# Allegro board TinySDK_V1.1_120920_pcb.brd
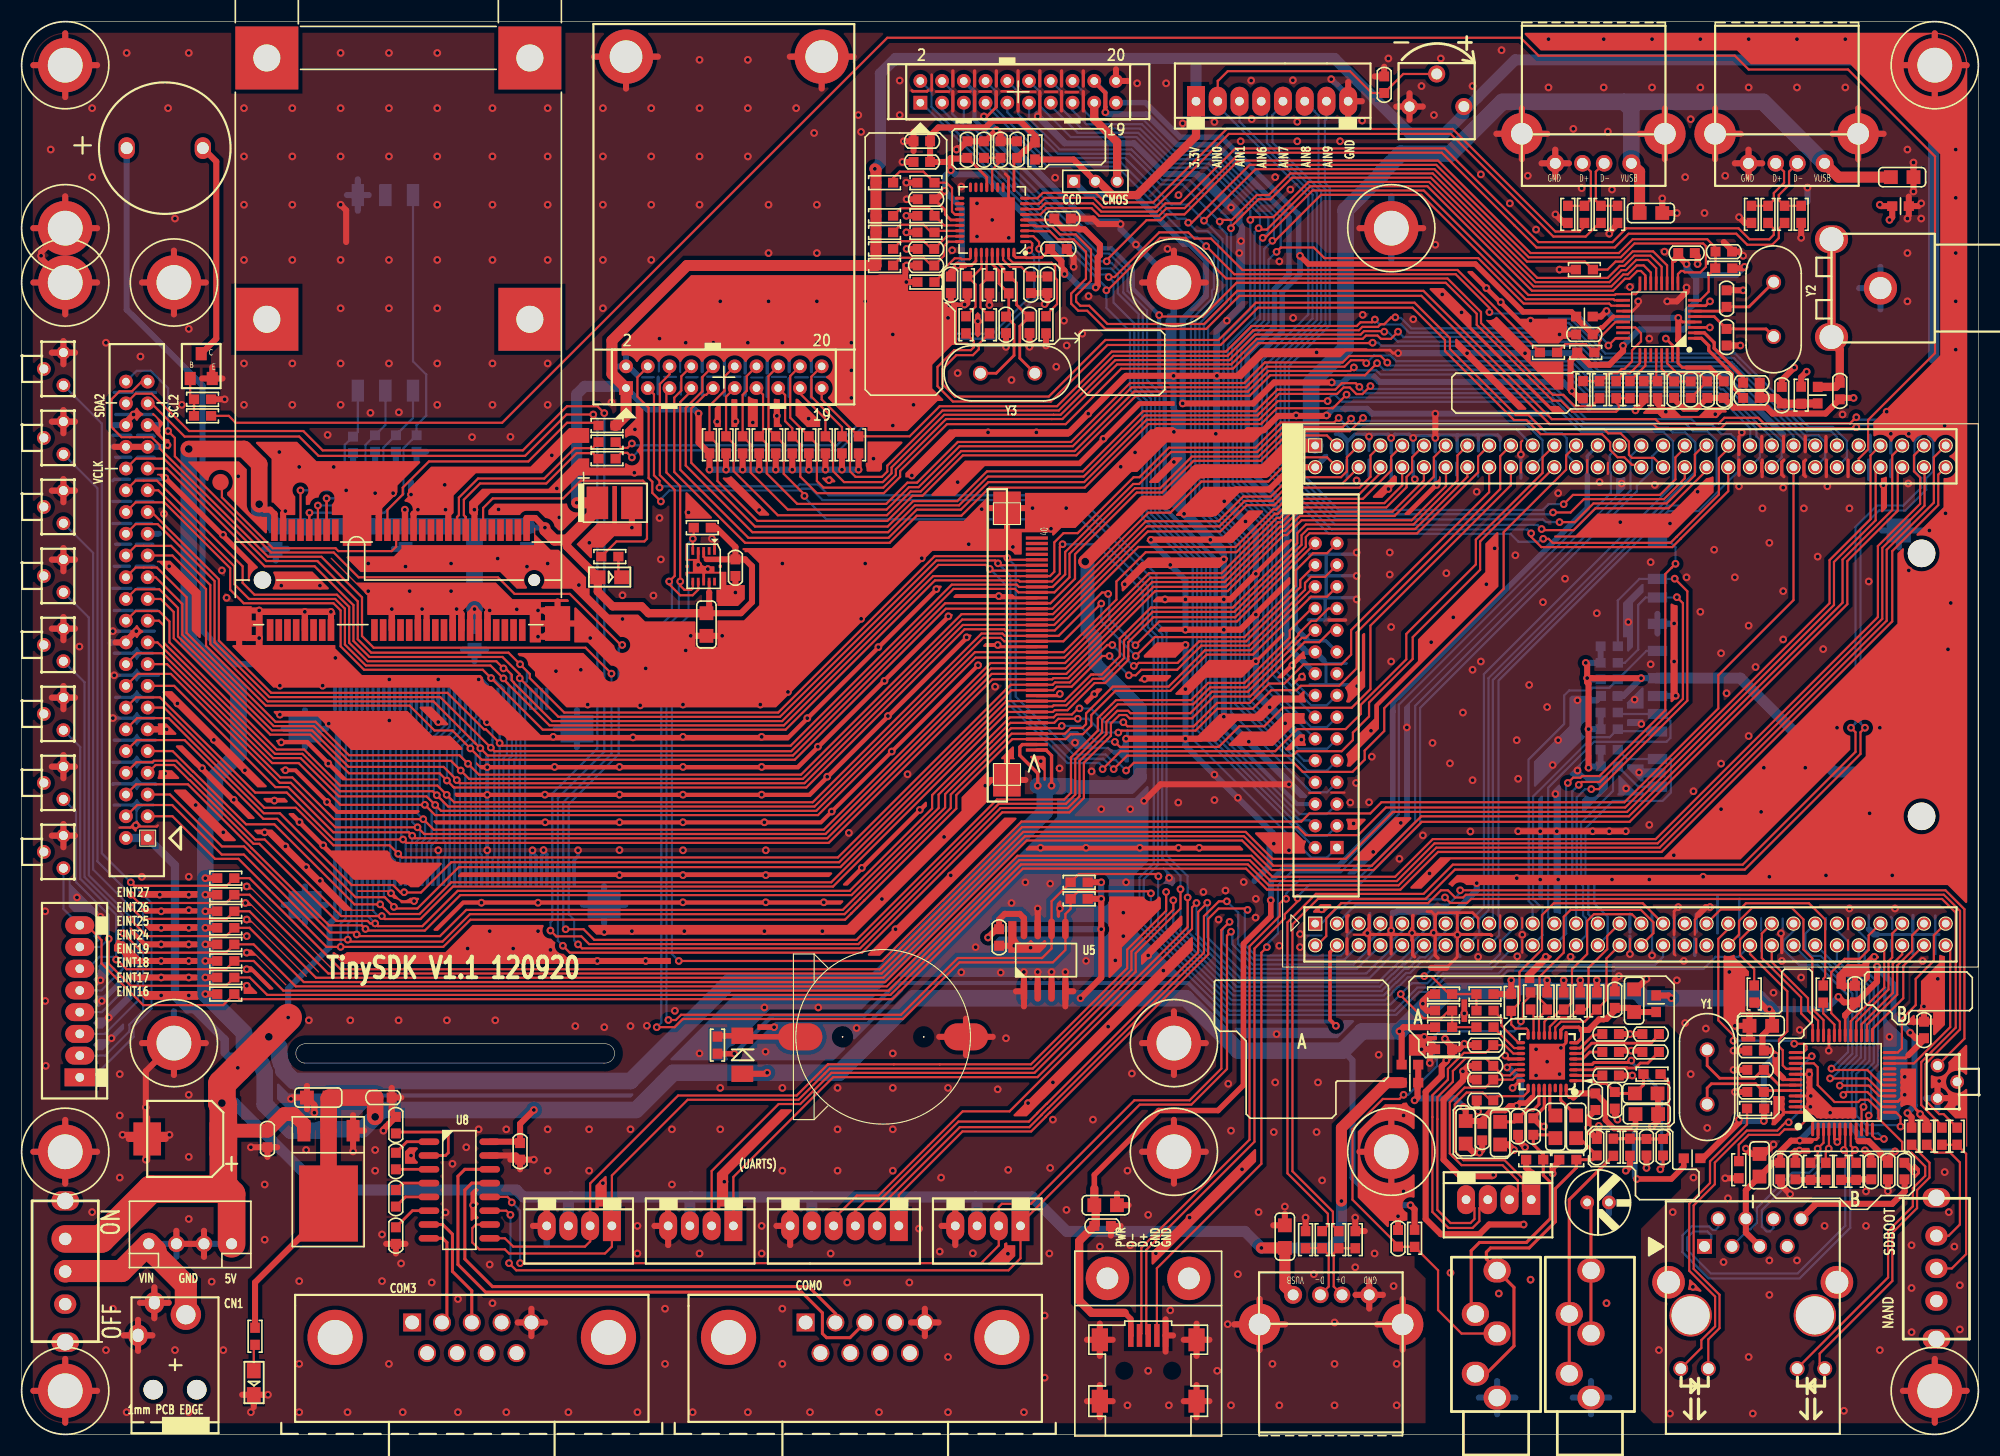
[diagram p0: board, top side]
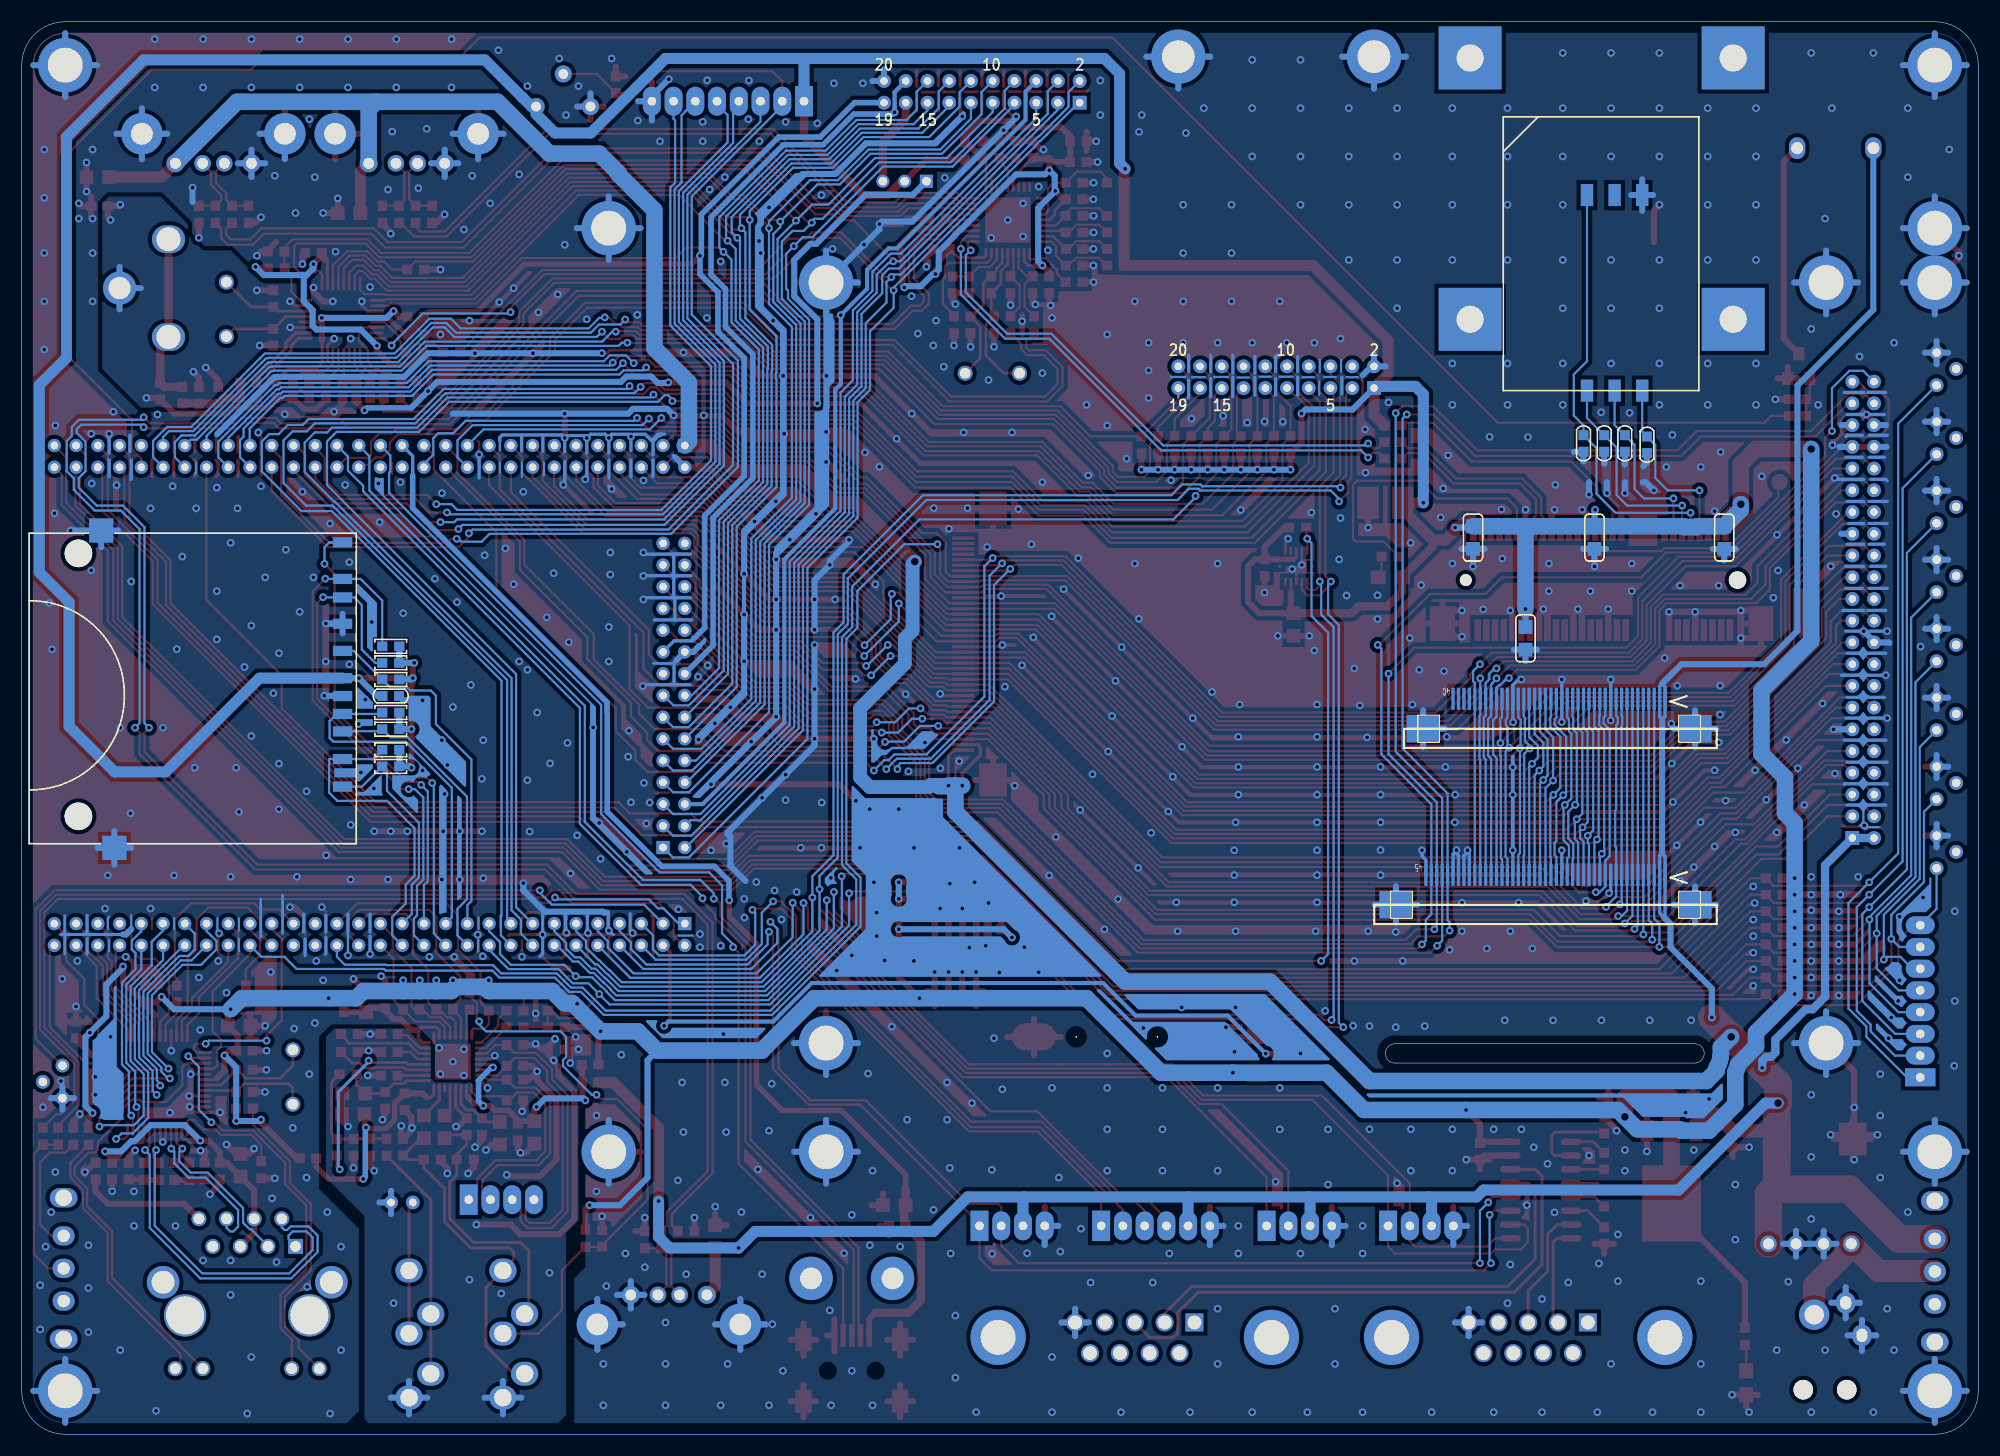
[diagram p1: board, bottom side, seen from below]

Outline 180 x 130 mm; copper layers: TOP, BOTTOM. Coordinates in mm from the lower left corner of the outline.
Outline path: 0,126 0,4 arc(1.17,1.17) 4,0 176,0 arc(178.83,1.17) 180,4 180,126 arc(178.83,128.83) 176,130 4,130 arc(1.17,128.83) 0,126 ; 26.01,35.94 53.57,35.94 arc(54.54,35.05) 53.57,34.16 26.01,34.16 arc(25.21,35.05) 26.01,35.94

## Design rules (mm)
net group DIFFPAIR42: nets XUHDM XUHDP
net group DIFFPAIR45: nets XUODM XUODP
net group DIFFPAIR46: nets DM9000_RX+ DM9000_RX-
net group DIFFPAIR47: nets DM9000_TX+ DM9000_TX-
net group DIFFPAIR48: nets N9616349 N9616353
net group DIFFPAIR49: nets N9609084 N9609088
net group DIFFPAIR50: nets DM2- DP2+
net group DIFFPAIR51: nets SPK_OUT_RN SPK_OUT_RP
net group DIFFPAIR52: nets SPK_OUT_LN SPK_OUT_LP
net group DIFFPAIR53: nets N9608868 N9608880
net group DIFFPAIR54: nets N9608680 N9608700
net group DIFFPAIR55: nets DM4- DP4+
net group 90OHM: nets N9607388 N9607392 USB_D+ USB_D-
net group PWR: nets N9607572

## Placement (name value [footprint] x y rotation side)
AVIN  -  [TVOUT]  166.5 109.98 180 top
BAT1  BATTERY  [BAT600]  71.63 36.58 90 top
BUZZER1  -  [SPEAKER]  9.91 118.37 0 top
C8  100uF/35V  [CAPSOP]  18.54 27.18 180 top
C9  104  [C0603]  22.61 27.94 270 top
C10  10uF  [C0805]  28.32 30.99 180 top
C11  104  [C0603]  32.51 30.99 0 top
C15  10uF/16V  [C0805]  161.04 37.59 180 top
C16  104  [C0603]  175.01 36.45 90 top
C17  104  [C0603]  168.66 39.75 90 top
C18  104  [C0603]  160.27 35.31 180 top
C19  15pF  [C0603]  160.28 33.54 180 top
C20  15pF  [C0603]  160.28 31.51 180 top
C21  104  [C0603]  173.21 24.99 270 top
C22  10uF/16V  [C0805]  159.88 23.72 90 top
C23  104  [C0603]  171.69 24.99 270 top
C24  104  [C0603]  161.78 24.99 270 top
C25  104  [C0603]  170.16 23.46 90 top
C26  104  [C0603]  163.18 23.46 90 top
C27  104  [C0603]  146.81 67.94 180 bottom
C28  104  [C0603]  89.92 46.48 270 top
C29  104  [C0603]  134.37 28.57 270 top
C30  10uF  [C0805]  132.84 28.83 270 top
C31  104  [C0603]  144.78 31.37 270 top
C32  10uF  [C0805]  148.46 29.46 0 top
C33  100pF  [C0603]  139.06 27.56 90 top
C34  100pF  [C0603]  144.91 25.65 90 top
C35  104  [C0603]  126.62 17.27 90 top
C36  1uF  [C0603]  151 27.18 270 top
C37  100pF  [C0603]  135.38 30.73 180 top
C38  100pF  [C0603]  135.38 32.64 180 top
C39  104  [C0603]  34.42 24.38 90 top
C40  104  [C0603]  34.42 29.21 270 top
C41  220pF  [C0603]  149.48 27.18 270 top
C42  1uF  [C0603]  149.1 35.18 0 top
C43  1uF  [C0603]  145.41 35.18 0 top
C44  1uF  [C0603]  145.41 33.02 0 top
C45  1uF  [C0603]  145.41 36.83 0 top
C46  1uF  [C0603]  150.62 36.83 180 top
C47  100pF  [C0603]  135.38 33.91 180 top
C48  100pF  [C0603]  135.38 35.81 180 top
C49  104  [C0603]  34.42 17.53 90 top
C50  104  [C0603]  146.56 39.24 90 top
C51  10uF/16V  [C0805]  98.68 21.08 0 top
C52  104  [C0603]  98.68 19.18 0 top
C53  104/NC  [C0603]  159.89 95.38 180 top
C54  10uF  [C0805]  148.34 38.86 90 top
C55  10uF  [C0805]  143 29.34 270 top
C56  10uF  [C0805]  141.1 29.34 270 top
C57  10uF  [C0805]  136.02 26.67 90 top
C58  104  [C0603]  137.67 29.08 270 top
C59  10uF  [C0805]  150.5 31.37 180 top
C60  104  [C0603]  146.56 31.5 270 top
C61  104  [C0603]  34.42 22.48 270 top
C62  104  [C0603]  65.66 78.99 90 top
C63  104  [C0603]  159.89 96.77 180 top
C64  104  [C0603]  125.35 123.44 90 top
C65  330pF  [C0603]  161.93 94.87 90 top
C67  10uF/16V  [C0805]  62.99 75.56 270 top
C68  104  [C0603]  45.85 26.8 270 top
C73  10u  [C0805]  171.96 115.7 0 top
C75  33pF  [C0603]  30.48 91.82 270 bottom
C76  33pF  [C0603]  34.42 91.95 270 bottom
C77  33pF  [C0603]  36.32 91.95 270 bottom
C78  33pF  [C0603]  32.51 91.95 270 bottom
C79  100uF  [C3528]  52.96 85.72 0 top
C80  104  [C0603]  83.57 117.09 180 top
C81  33pF  [C0603]  90.55 102.87 270 top
C82  104  [C0603]  85.47 106.55 270 top
C83  104  [C0603]  83.95 109.09 180 top
C84  104  [C0603]  92.84 106.55 270 top
C85  104  [C0603]  83.95 107.57 180 top
C86  104  [C0603]  95 111.89 0 top
C87  104  [C0603]  87 117.47 90 top
C88  104  [C0603]  91.57 117.47 90 top
C89  104  [C0603]  83.57 119 180 top
C90  1uF  [C0603]  94.36 106.55 270 top
C91  104  [C0603]  88.52 117.47 90 top
C92  1uF  [C0603]  90.05 117.47 90 top
C93  1uF  [C0603]  83.95 113.66 180 top
C94  1uF  [C0603]  94.62 109.09 0 top
C95  33pF  [C0603]  92.71 102.87 270 top
C96  10u  [C0805]  148.84 112.39 0 top
C97  10u  [C0805]  116.21 17.15 90 top
C104  330pF  [C0603]  167.26 96.77 270 top
C105  104  [C0603]  153.92 108.71 180 top
C106  104  [C0603]  143 101.22 0 top
C107  104  [C0603]  156.59 95.38 90 top
C108  22pF  [C0603]  156.84 103.76 90 top
C109  22pF  [C0603]  156.84 101.73 270 top
C110  1uF  [C0603]  153.54 96.9 270 top
C111  1uF  [C0603]  152.02 95.38 90 top
C112  1uF  [C0603]  155.07 95.38 90 top
C113  104  [C0603]  157.35 108.84 180 top
C142  10uF  [C0805]  23.37 83.57 270 bottom
C144  10uF  [C0805]  35.31 83.57 270 bottom
C145  10uF  [C0805]  41.66 74.3 270 bottom
C148  10uF  [C0805]  46.48 83.57 270 bottom
CAMERA  CON20A  [SDWIFI-NH]  91.67 123.55 0 top
CN1  DC_JACK  [DC023B]  14.1 6.35 90 top
COM0  CONNECTOR DB9  [DB9RA_M]  77.6 10.29 90 top
COM3  CONNECTOR DB9  [DB9RA_M]  41.4 10.29 90 top
CON1  CON4  [SIP4-FA2]  92.97 19.18 180 top
CON2  CON6  [SIP6-FA2]  75.69 19.18 180 top
CON3  CON4  [SIP4-FA2]  66.55 19.18 180 top
CON4  CON4  [SIP4-FA2]  55.37 19.18 180 top
CON5  CON4  [CON4-B]  15.5 17.53 180 top
CON6  CON8  [SIP8-FA2]  113.03 122.68 0 top
CON7  CON8  [SIP8-FA2]  5.34 37.85 90 top
CON8  MF210_miniPCIe  [MINI_PCIEX1-52P-4H]  34.65 78.62 0 top
CON10  SD/MMC CARD  [SDCARD]  169.04 61.98 0 bottom
CON12  J1X4_2.0PH  [SIP4-FA]  139.96 21.59 180 top
D1  4148  [D1206]  66.29 33.17 90 top
D4  GREEN LED  [LED]  53 78.86 0 top
FB1  0R/NC  [L0603]  127.71 34.02 0 top
FB2  0R  [L0603]  153.67 25.4 180 top
FB3  0R  [L0603]  127.71 32.36 0 top
FB5  0R  [L0603]  150.37 39.62 270 top
H1  CON1  [H1]  4 4 0 top
H2  CON1  [H1]  4 126 0 top
H3  CON1  [H1]  176 126 0 top
H4  CON1  [H1]  176 4 0 top
H5  CON1  [H1]  4 26 0 top
H6  CON1  [H1]  106 26 0 top
H7  CON1  [H1]  4 106 0 top
H8  CON1  [H1]  4 111 0 top
H9  CON1  [H1]  14 36 0 top
H10  CON1  [H1]  14 106 0 top
H11  CON1  [H1]  106 36 0 top
H12  CON1  [H1]  126 26 0 top
H13  CON1  [H1]  106 106 0 top
H14  CON1  [H1]  126 111 0 top
J1  CON3  [SIP3S]  96.78 115.32 0 top
K1  SW PUSHBUTTON  [KEY-A06]  2.03 98.05 270 top
K2  SW PUSHBUTTON  [KEY-A06]  2.03 91.7 270 top
K3  SW PUSHBUTTON  [KEY-A06]  2.03 85.35 270 top
K4  SW PUSHBUTTON  [KEY-A06]  2.03 79 270 top
K5  SW PUSHBUTTON  [KEY-A06]  2.03 72.65 270 top
K6  SW PUSHBUTTON  [KEY-A06]  2.03 66.3 270 top
K7  SW PUSHBUTTON  [KEY-A06]  2.03 59.95 270 top
K8  SW PUSHBUTTON  [KEY-A06]  2.03 53.6 270 top
L6  3.3uH/0R  [L0603]  165.23 95.63 270 top
L8  0R  [L0603]  143.76 102.87 0 top
L9  0R  [L0603]  172.85 113.03 0 top
LAN1  -  [HR911105A]  159.26 21.44 180 top
LCD1  LCD-888  [CON-FPC-P05-45P]  25.65 52.45 0 bottom
LCD2  LCD-888  [CON-FPC-P05-40P]  94.36 59.82 90 top
LCD3  LCD-888  [CON-FPC-P05-40P]  25.65 68.66 0 bottom
LCD4  CON44A  [IDC44S2]  10.42 74.42 90 top
LED_3.3  RED  [LED]  21.34 5.84 270 top
MIC1  MIC  [MIC2]  144.02 21.34 0 top
MIC2  PHONEJACK STEREO SW  [EARJACK5]  144.27 16.24 270 top
MINIUSB1  USBOTG  [MINIUSB_ANT]  103.63 5.84 0 top
P1  SIMCARD  [SIM-0011]  36.2 114.05 180 bottom
PERST_N  TP  [PADC15]  18.29 87.63 0 top
Q2  3904  [SOT-23-Q]  16.51 98.31 0 top
R1  0R  [R0603]  176.66 27.43 90 top
R2  0R  [R0603]  178.05 27.43 270 top
R3  0R  [R0603]  175.26 27.43 270 top
R4  1K  [R0603]  21.46 9.02 270 top
R5  10K  [R0603]  159.38 40.51 270 top
R6  1K  [R0603]  16.64 93.73 0 top
R7  0R  [R0603]  165.74 40.51 90 top
R8  6.8K,1%  [R0603]  157.97 24.35 270 top
R9  10K  [R0603]  97.28 50.8 180 top
R10  10K  [R0603]  97.28 49.28 180 top
R11  100K  [R0603]  64.01 35.81 270 top
R12  10K  [R0603]  64.8 91.06 270 top
R13  10K  [R0603]  67.84 91.06 270 top
R14  10K  [R0603]  70.89 91.06 270 top
R16  10K  [R0603]  16.64 95.25 180 top
R18  10K  [R0603]  73.94 91.06 270 top
R19  10K  [R0603]  76.99 91.06 270 top
R20  1K  [R0603]  159.51 29.98 180 top
R21  1K  [R0603]  173.86 27.43 270 top
R23  10K  [R0603]  66.32 91.06 90 top
R24  51R  [R0603]  167.37 24.2 270 top
R25  51R  [R0603]  168.77 24.2 270 top
R26  51R  [R0603]  164.57 24.2 270 top
R27  10K  [R0603]  63.27 91.06 90 top
R28  10K  [R0603]  69.37 91.06 90 top
R29  51R  [R0603]  165.97 24.2 270 top
R30  4.7K  [R0603]  62.61 83.44 180 top
R31  4.7K  [R0603]  134.62 40.51 0 top
R32  4.7K  [R0603]  130.81 38.99 180 top
R34  10K  [R0603]  72.42 91.06 90 top
R35  10K  [R0603]  18.77 51.18 180 top
R37  10K  [R0603]  18.77 49.66 180 top
R38  10K  [R0603]  146.05 62.99 180 bottom
R39  10K  [R0603]  18.77 48.13 180 top
R40  10K  [R0603]  18.77 46.61 180 top
R41  10K  [R0603]  146.05 69.47 180 bottom
R42  10K  [R0603]  146.05 64.9 180 bottom
R43  10K  [R0603]  18.77 45.09 0 top
R46  10K  [R0603]  142.24 25.27 0 top
R47  10K  [R0603]  139.19 25.27 0 top
R49  100K  [R0603]  128.14 18.03 90 top
R51  75R  [R0603]  163.7 95.63 90 top
R57  0R  [R0603]  134.62 38.99 0 top
R58  0R  [R0603]  134.62 37.47 0 top
R59  2.2K  [R0603]  149.99 33.15 180 top
R60  10K  [R0603]  75.46 91.06 90 top
R62  47K/NC  [R0603]  147.96 26.42 90 top
R63  0R  [R0603]  130.81 35.43 0 top
R64  10K  [R0603]  18.77 43.56 0 top
R65  10K  [R0603]  18.77 42.04 0 top
R66  10K  [R0603]  18.77 40.51 0 top
R67  100R  [R0603]  146.43 26.42 90 top
R71  10K  [R0603]  146.05 66.42 180 bottom
R72  10K  [R0603]  146.05 72.52 180 bottom
R73  10K  [R0603]  146.05 70.99 180 bottom
R74  10K  [R0603]  146.05 61.47 180 bottom
R75  10K  [R0603]  53.85 92.84 0 top
R76  200R  [R0603]  54.1 80.77 0 top
R80  22R  [R0603]  53.85 89.79 0 top
R81  22R  [R0603]  53.85 91.31 0 top
R82  0R  [R0603]  89.03 102.11 270 top
R89  22R  [R0603]  162.18 112.27 90 top
R90  22R  [R0603]  160.66 112.27 90 top
R91  NC  [R0603]  163.71 112.27 270 top
R92  0R  [R0603]  138.81 39.88 270 top
R93  NC  [R0603]  159.13 112.27 270 top
R94  NC  [R0603]  146.81 112.27 270 top
R95  22R  [R0603]  145.29 112.27 90 top
R96  0R  [R0603]  86.87 102.11 270 top
R97  22R  [R0603]  143.77 112.27 90 top
R99  NC  [R0603]  142.24 112.27 270 top
R107  NC  [R0603]  79.38 112.14 180 top
R108  NC  [R0603]  79.38 115.19 180 top
R109  NC  [R0603]  118.11 17.91 90 top
R110  22R  [R0603]  119.64 17.91 270 top
R111  10K  [R0603]  83.19 106.04 0 top
R112  22R  [R0603]  121.16 17.91 270 top
R113  NC  [R0603]  122.68 17.91 90 top
R114  10K  [R0603]  79.38 109.09 180 top
R115  10K  [R0603]  83.19 110.61 0 top
R116  10K  [R0603]  83.19 112.14 0 top
R117  10K  [R0603]  83.19 115.19 0 top
R118  0R  [R0603]  93.22 118.11 270 top
R119  0R  [R0603]  79.38 107.57 180 top
R121  12K,1%  [R0603]  94.24 102.11 270 top
R126  NC  [R0603]  130.81 37.47 180 top
R127  NC  [R0603]  130.81 40.51 180 top
R128  10K  [R0603]  137.03 39.75 90 top
R129  10K  [R0603]  140.34 39.88 90 top
R130  1M  [R0603]  90.81 105.79 90 top
R131  10K  [R0603]  141.86 39.88 90 top
R132  10K  [R0603]  143.38 39.88 90 top
R133  10K  [R0603]  144.91 39.88 90 top
R134  NC  [R0603]  79.38 110.61 180 top
R135  NC  [R0603]  89.03 105.79 270 top
R136  NC  [R0603]  87 105.79 270 top
R137  0R  [R0603]  147.96 96.14 270 top
R138  NC  [R0603]  146.69 96.14 270 top
R139  10K  [R0603]  143.76 107.19 0 top
R140  0R  [R0603]  140.46 99.57 0 top
R141  0R  [R0603]  145.16 96.14 90 top
R142  10K  [R0603]  150.5 96.14 90 top
R143  1.2K/NC  [R0603]  143.89 99.57 0 top
R144  1.2K/NC  [R0603]  143.64 96.14 270 top
R145  0R  [R0603]  149.22 96.14 90 top
R146  10K  [R0603]  156.59 107.31 180 top
RST  SW PUSHBUTTON  [KEY-A06]  178.05 32.44 90 top
S1  SW-DIP4  [SW35]  4 15 270 top
S2  SW-DIP4  [SW35]  176.15 15.24 90 top
SDIO  CON20A  [SDWIFI-2H]  64.59 97.28 0 top
SPK1  PHONEJACK STEREO SW  [EARJACK5]  135.64 16.24 270 top
TINY210  TinyCore  [TINY6410_2]  116 43 0 top
U2  AMS1086CM-3.3  [TO-252]  30.48 27.94 180 top
U4  DM9000AEP  [LQFP48FA]  167.51 32.38 0 top
U5  AT24LC04  [SOP8]  92.2 40.77 90 top
U6  WM8960GEFL  [QFN32-19P7-TH]  140.34 34.29 180 top
U7  MMA7660FC  [DFN10-19P7X111-2TH]  62.74 79.88 180 top
U8  SP3232  [SOP16]  37.47 26.92 0 top
U9  TVP5150  [S-PQFP-G32]  150.62 102.62 180 top
U11  USB2514B_QFN36_MIN  [QFN36-19P7]  89.28 111.76 180 top
USBH1  USB  A  [USB-A2]  165.86 116.97 0 top
USBH2  USB  A  [USB-A2]  148.08 116.97 0 top
USBH3  USB  A  [USB-A2]  116.97 12.83 180 top
W1  10K  [VR3_7X7]  129.03 123.19 0 top
Y1  25MHz  [OSC2PR-1]  155.06 35.32 270 top
Y2  14.31818MHz  [OSC2PR-1]  161.18 101.09 90 top
Y3  24MHz  [OSC2PR-1]  88.27 97.65 0 top

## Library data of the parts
AVIN = TVOUT
BAT1 = BATTERY_3
BUZZER1 = SPEAKER
C8 C10 C15 C22 C51 C67 C79 = CAP
C9 C11 C16-C21 C23-C50 C52-C65 C68 C73 C75-C78 C80 C82-C89 C91 C96 C97 C104-C113 C142 C144 C145 C148 = CAP NP
C81 C94 C95 = C
C90 C92 = 1.0uF-6.3V-10%-X5R-0402
C93 = 1.0uF-16V-10%-X5R-0603
CAMERA = CON20A
CN1 = CON3_3
COM0 COM3 = CONNECTOR DB9_2
CON1 CON3-CON5 = CON4
CON2 = CON6
CON6 CON7 = CON8
CON8 = CON50A_5
CON10 = SD_0
CON12 = J1X4_1
D1 = DIODE
D4 LED_3.3 = LED
FB1-FB3 FB5 L6 L8 L9 = INDUCTOR
H1-H14 = CON1
J1 = CON3
K1-K8 RST = SW PUSHBUTTON_0
LAN1 = HR911105A
LCD1 = LCD-888_1
LCD2 LCD3 = LCD-888_2
LCD4 = CON40A_0
MIC1 = MIC
MIC2 SPK1 = PHONEJACK STEREO SW
MINIUSB1 = USB_A/B_2
P1 = SIMCARD_0
PERST_N = TP
Q2 = NPN-BEC
R1-R14 R16 R18-R21 R23-R32 R34 R35 R37-R43 R46 R47 R49 R57-R60 R62-R67 R71-R76 R80-R82 R89-R97 R99 R107-R119 R126-R136 = R
R51 R137-R146 = RESISTOR
R121 = 12.0K-1/16W-1%-0603
S1 S2 = CON5
SDIO = CON20A_4
TINY210 = TinyCore
U2 = AMS1117
U4 = DM9000AEP
U5 = AT24LC04
U6 = WM8960GEFL_0
U7 = MMA7660FC
U8 = SP3232
U9 = TVP5150
U11 = USB2514B_QFN36_MIN
USBH1-USBH3 = USBPORT_0
W1 = RESISTOR VAR_0
Y1-Y3 = CRYSTAL

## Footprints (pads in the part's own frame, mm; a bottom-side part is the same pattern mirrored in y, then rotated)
BAT600
  oval 2.489x4.064 smd: 1(0,0) 2(0,-15.24)
  round 0.127 hole 1.194: 3(0,-3.886) 4(0,-11.354)
C0603
  rect 0.914x0.914 smd: 1(0,0) 2(1.524,0)
C0805
  rect 1.27x1.27 smd: 1(0,0) 2(2.083,0)
C3528
  rect 1.981x2.997 smd: 1(0,0) 2(3.175,0)
CAPSOP
  rect 2.54x3.048 smd: 1(0,0) 2(7,0)
CON4-B
  round 1.524 hole 1.016: 1(-3.81,0) 2(-1.27,0) 3(1.27,0) 4(3.81,0)
CON-FPC-P05-40P
  rect 0.305x2.032 smd: 1(3.16,0.968) 2(3.66,0.968) 3(4.16,0.968) 4(4.66,0.968) 5(5.16,0.968) 6(5.66,0.968) 7(6.161,0.968) 8(6.661,0.968) 9(7.161,0.968) 10(7.661,0.968) 11(8.161,0.968) 12(8.661,0.968) 13(9.161,0.968) 14(9.661,0.968) 15(10.162,0.968) 16(10.662,0.968) 17(11.162,0.968) 18(11.662,0.968) 19(12.162,0.968) 20(12.662,0.968) 21(13.162,0.968) 22(13.662,0.968) 23(14.163,0.968) 24(14.663,0.968) 25(15.163,0.968) 26(15.663,0.968) 27(16.163,0.968) 28(16.663,0.968) 29(17.163,0.968) 30(17.663,0.968) 31(18.164,0.968) 32(18.664,0.968) 33(19.164,0.968) 34(19.664,0.968) 35(20.164,0.968) 36(20.664,0.968) 37(21.164,0.968) 38(21.664,0.968) 39(22.165,0.968) 40(22.665,0.968)
  rect 3.048x2.54 smd: A(0.399,3.726) B(25.42,3.713)
CON-FPC-P05-45P
  rect 0.305x2.032 smd: 1(3.16,0.968) 2(3.66,0.968) 3(4.16,0.968) 4(4.66,0.968) 5(5.16,0.968) 6(5.66,0.968) 7(6.16,0.968) 8(6.661,0.968) 9(7.161,0.968) 10(7.661,0.968) 11(8.161,0.968) 12(8.661,0.968) 13(9.161,0.968) 14(9.661,0.968) 15(10.161,0.968) 16(10.662,0.968) 17(11.162,0.968) 18(11.662,0.968) 19(12.162,0.968) 20(12.662,0.968) 21(13.162,0.968) 22(13.662,0.968) 23(14.163,0.968) 24(14.663,0.968) 25(15.163,0.968) 26(15.663,0.968) 27(16.163,0.968) 28(16.663,0.968) 29(17.163,0.968) 30(17.663,0.968) 31(18.163,0.968) 32(18.664,0.968) 33(19.164,0.968) 34(19.664,0.968) 35(20.164,0.968) 36(20.664,0.968) 37(21.164,0.968) 38(21.664,0.968) 39(22.164,0.968) 40(22.665,0.968) 41(23.165,0.968) 42(23.665,0.968) 43(24.165,0.968) 44(24.665,0.968) 45(25.165,0.968)
  rect 3.048x2.54 smd: A(0.399,3.726) B(27.92,3.714)
D1206
  rect 1.5x2 smd: 1(0.009,-0.006) 2(3.51,-0.006)
DB9RA_M
  rect 1.651x1.651 hole 1.27: 1(0,5.486)
  round 1.651 hole 1.27: 2(0,2.743) 3(0,0) 4(0,-2.743) 5(0,-5.486) 6(-2.819,4.115) 7(-2.819,1.372) 8(-2.819,-1.372) 9(-2.819,-4.115)
  round 5.08 hole 3.2: 10(-1.372,12.573) 11(-1.372,-12.573)
DC023B
  round 1.803 hole 1.803 unplated: (-2.25,2) (-2.25,-2)
  round 2.794 hole 1.778: 1(4.65,-1)
  oval 1.981x1.778 hole 1.219x1.016: 2(5.75,1.9) 3(2.75,3.4)
DFN10-19P7X111-2TH
  rect 0.254x0.711 smd: 1(-1,-1.412) 2(-0.5,-1.412) 3(0,-1.412) 4(0.5,-1.412) 5(1,-1.412) 6(1,1.412) 7(0.5,1.412) 8(0,1.412) 9(-0.5,1.412) 10(-1,1.412)
  rect 0.3x0.254 smd: M1(1.524,0) M2(-1.524,0)
EARJACK5
  oval 2.2x2.5 hole 1.6: 1(5.17,-1.903) 2(6.97,0.097) 3(1.17,0.097) 4(10.67,-1.903) 5(12.87,0.097)
H1
  round 5 hole 3.2: 1(0,0)
HR911105A
  round 3.9 hole 3.5 unplated: (-5.707,10.498) (5.723,10.498)
  rect 1.372x1.372 hole 0.991: 1(4.453,4.148)
  round 1.372 hole 0.991: 2(3.183,1.608) 3(1.913,4.148) 4(0.643,1.608) 5(-0.627,4.148) 6(-1.897,1.608) 7(-3.167,4.148) 8(-4.437,1.608) 9(6.633,15.398) 10(4.093,15.398) 11(-4.077,15.398) 12(-6.617,15.398)
  round 2.997 hole 2.1: M3(-7.737,7.448) M4(7.753,7.448)
IDC44S2
  rect 1.27x1.27 hole 0.7: 1(-19.547,-1.17)
  round 1.27 hole 0.7: 2(-19.547,0.83) 3(-17.547,-1.17) 4(-17.547,0.83) 5(-15.547,-1.17) 6(-15.547,0.83) 7(-13.547,-1.17) 8(-13.547,0.83) 9(-11.547,-1.17) 10(-11.547,0.83) 11(-9.547,-1.17) 12(-9.547,0.83) 13(-7.547,-1.17) 14(-7.547,0.83) 15(-5.547,-1.17) 16(-5.547,0.83) 17(-3.547,-1.17) 18(-3.547,0.83) 19(-1.547,-1.17) 20(-1.547,0.83) 21(0.453,-1.17) 22(0.453,0.83) 23(2.453,-1.17) 24(2.453,0.83) 25(4.453,-1.17) 26(4.453,0.83) 27(6.453,-1.17) 28(6.453,0.83) 29(8.453,-1.17) 30(8.453,0.83) 31(10.453,-1.17) 32(10.453,0.83) 33(12.453,-1.17) 34(12.453,0.83) 35(14.453,-1.17) 36(14.453,0.83) 37(16.453,-1.17) 38(16.453,0.83) 39(18.453,-1.17) 40(18.453,0.83) 41(20.453,-1.17) 42(20.453,0.83) 43(22.453,-1.17) 44(22.453,0.83)
KEY-A06
  round 1.27 hole 0.787: 1(1.5,1.8) 2(-1.5,1.8) 3(0,0)
L0603
  rect 0.94x0.889 smd: 1(-0.762,0) 2(0.762,0)
LED
  rect 1.4x1.27 smd: 1(-0.002,0.008) 2(2.207,0.008)
LQFP48FA
  oval 0.279x1.27 smd: 1(-2.75,-4.327) 2(-2.25,-4.327) 3(-1.75,-4.327) 4(-1.25,-4.327) 5(-0.75,-4.327) 6(-0.25,-4.327) 7(0.25,-4.327) 8(0.75,-4.327) 9(1.25,-4.327) 10(1.75,-4.327) 11(2.25,-4.327) 12(2.75,-4.327) 25(2.75,4.327) 26(2.25,4.327) 27(1.75,4.327) 28(1.25,4.327) 29(0.75,4.327) 30(0.25,4.327) 31(-0.25,4.327) 32(-0.75,4.327) 33(-1.25,4.327) 34(-1.75,4.327) 35(-2.25,4.327) 36(-2.75,4.327)
  oval 1.27x0.279 smd: 13(4.327,-2.75) 14(4.327,-2.25) 15(4.327,-1.75) 16(4.327,-1.25) 17(4.327,-0.75) 18(4.327,-0.25) 19(4.327,0.25) 20(4.327,0.75) 21(4.327,1.25) 22(4.327,1.75) 23(4.327,2.25) 24(4.327,2.75) 37(-4.327,2.75) 38(-4.327,2.25) 39(-4.327,1.75) 40(-4.327,1.25) 41(-4.327,0.75) 42(-4.327,0.25) 43(-4.327,-0.25) 44(-4.327,-0.75) 45(-4.327,-1.25) 46(-4.327,-1.75) 47(-4.327,-2.25) 48(-4.327,-2.75)
MIC2
  round 1.27 hole 0.711: 1(0,0) 2(2,0)
MINI_PCIEX1-52P-4H
  round 1.6 hole 1.6 unplated: (-12.5,0)
  rect 5.791x5.791 hole 2.489: (-12.1,48.05) (-12.1,24) (12.1,48.05) (12.1,24)
  round 1.092 hole 1.092 unplated: (12.5,0)
  rect 0.61x2.007 smd: 1(-11.8,-4.6) 2(-11.4,4.6) 3(-11,-4.6) 4(-10.6,4.6) 5(-10.2,-4.6) 6(-9.8,4.6) 7(-9.4,-4.6) 8(-9,4.6) 9(-8.6,-4.6) 10(-8.2,4.6) 11(-7.8,-4.6) 12(-7.4,4.6) 13(-7,-4.6) 14(-6.6,4.6) 15(-6.2,-4.6) 16(-5.8,4.6) 17(-2.2,-4.6) 18(-1.8,4.6) 19(-1.4,-4.6) 20(-1,4.6) 21(-0.6,-4.6) 22(-0.2,4.6) 23(0.2,-4.6) 24(0.6,4.6) 25(1,-4.6) 26(1.4,4.6) 27(1.8,-4.6) 28(2.2,4.6) 29(2.6,-4.6) 30(3,4.6) 31(3.4,-4.6) 32(3.8,4.6) 33(4.2,-4.6) 34(4.6,4.6) 35(5,-4.6) 36(5.4,4.6) 37(5.8,-4.6) 38(6.2,4.6) 39(6.6,-4.6) 40(7,4.6) 41(7.4,-4.6) 42(7.8,4.6) 43(8.2,-4.6) 44(8.6,4.6) 45(9,-4.6) 46(9.4,4.6) 47(9.8,-4.6) 48(10.2,4.6) 49(10.6,-4.6) 50(11,4.6) 51(11.4,-4.6) 52(11.8,4.6)
  rect 2.311x3.2 smd: M1(-14.65,-4) M2(14.65,-4)
MINIUSB_ANT
  round 4 hole 2 unplated: (-3.75,8.5) (3.75,8.5)
  round 0 hole 0.889 unplated: (-2.2,0) (2.2,0)
  rect 0.508x2.108 smd: 1(-1.6,3.25) 2(-0.8,3.25) 3(0,3.25) 4(0.8,3.25) 5(1.6,3.25)
  rect 1.499x2.108 smd: 6(4.45,2.85) 7(-4.45,2.85) 8(-4.45,-2.8) 9(4.45,-2.8)
OSC2PR-1
  round 1.372 hole 0.991: 1(-0.064,0) 2(4.94,0)
PADC15
  round 1.5 smd: 1(0,0)
QFN32-19P7-TH
  oval 0.813x0.305 smd: 1(-2.425,1.75) 2(-2.425,1.25) 3(-2.425,0.75) 4(-2.425,0.25) 5(-2.425,-0.25) 6(-2.425,-0.75) 7(-2.425,-1.25) 8(-2.425,-1.75) 17(2.425,-1.75) 18(2.425,-1.25) 19(2.425,-0.75) 20(2.425,-0.25) 21(2.425,0.25) 22(2.425,0.75) 23(2.425,1.25) 24(2.425,1.75)
  oval 0.305x0.813 smd: 9(-1.75,-2.425) 10(-1.25,-2.425) 11(-0.75,-2.425) 12(-0.25,-2.425) 13(0.25,-2.425) 14(0.75,-2.425) 15(1.25,-2.425) 16(1.75,-2.425) 25(1.75,2.425) 26(1.25,2.425) 27(0.75,2.425) 28(0.25,2.425) 29(-0.25,2.425) 30(-0.75,2.425) 31(-1.25,2.425) 32(-1.75,2.425)
  rect 3.302x3.302 smd: G1(0,0)
QFN36-19P7
  oval 0.889x0.279 smd: 1(-3,2) 2(-3,1.5) 3(-3,1) 4(-3,0.5) 5(-3,0) 6(-3,-0.5) 7(-3,-1) 8(-3,-1.5) 9(-3,-2) 19(3,-2) 20(3,-1.5) 21(3,-1) 22(3,-0.5) 23(3,0) 24(3,0.5) 25(3,1) 26(3,1.5) 27(3,2)
  oval 0.279x0.889 smd: 10(-2,-3) 11(-1.5,-3) 12(-1,-3) 13(-0.5,-3) 14(0,-3) 15(0.5,-3) 16(1,-3) 17(1.5,-3) 18(2,-3) 28(2,3) 29(1.5,3) 30(1,3) 31(0.5,3) 32(0,3) 33(-0.5,3) 34(-1,3) 35(-1.5,3) 36(-2,3)
  rect 4.166x4.166 smd: 37(0,0)
R0603
  rect 0.94x0.889 smd: 1(-0.787,0) 2(0.787,0)
S-PQFP-G32
  rect 1.27x0.254 smd: 1(-3.3,1.75) 2(-3.3,1.25) 3(-3.3,0.75) 4(-3.3,0.25) 5(-3.3,-0.25) 6(-3.3,-0.75) 7(-3.3,-1.25) 8(-3.3,-1.75) 17(3.3,-1.75) 18(3.3,-1.25) 19(3.3,-0.75) 20(3.3,-0.25) 21(3.3,0.25) 22(3.3,0.75) 23(3.3,1.25) 24(3.3,1.75)
  rect 0.254x1.27 smd: 9(-1.75,-3.3) 10(-1.25,-3.3) 11(-0.75,-3.3) 12(-0.25,-3.3) 13(0.25,-3.3) 14(0.75,-3.3) 15(1.25,-3.3) 16(1.75,-3.3) 25(1.75,3.3) 26(1.25,3.3) 27(0.75,3.3) 28(0.25,3.3) 29(-0.25,3.3) 30(-0.75,3.3) 31(-1.25,3.3) 32(-1.75,3.3)
SDCARD
  round 2.54 hole 2.54 unplated: (5.748,-19.095) (5.748,5.104)
  rect 1.778x0.94 smd: 1(-18.552,-0.168) 2(-18.552,-2.708) 3(-18.552,-5.967) 4(-18.552,-7.612) 5(-18.552,-10.119) 6(-18.552,-12.619) 7(-18.552,-15.039) 8(-18.552,-16.744) 9(-18.552,2.372) 10(-18.552,-20.104) 11(-18.552,-4.316)
  rect 2.235x2.235 smd: 12(2.438,8.009) 13(3.652,-21.199)
SDWIFI-2H
  rect 1.27x1.27 hole 0.7: 1(-9,-1)
  round 1.27 hole 0.7: 2(-9,1) 3(-7,-1) 4(-7,1) 5(-5,-1) 6(-5,1) 7(-3,-1) 8(-3,1) 9(-1,-1) 10(-1,1) 11(1,-1) 12(1,1) 13(3,-1) 14(3,1) 15(5,-1) 16(5,1) 17(7,-1) 18(7,1) 19(9,-1) 20(9,1)
  round 5 hole 3: A(9,29.5) B(-9,29.5)
SDWIFI-NH
  rect 1.27x1.27 hole 0.7: 1(-9,-1)
  round 1.27 hole 0.7: 2(-9,1) 3(-7,-1) 4(-7,1) 5(-5,-1) 6(-5,1) 7(-3,-1) 8(-3,1) 9(-1,-1) 10(-1,1) 11(1,-1) 12(1,1) 13(3,-1) 14(3,1) 15(5,-1) 16(5,1) 17(7,-1) 18(7,1) 19(9,-1) 20(9,1)
SIM-0011
  rect 1.143x2.032 smd: 1(5.28,-18) 2(2.74,-18) 3(0.2,-18) 4(5.28,0) 5(2.74,0) 6(0.2,0)
SIP3S
  rect 1.2x1.2 hole 0.8: 1(0,0)
  round 1.2 hole 0.8: 2(2,0) 3(4,0)
SIP4-FA
  rect 1.651x2.8 hole 0.8: 1(1.08,0)
  oval 1.651x2.667 hole 0.8: 2(3.08,0) 3(5.08,0) 4(7.08,0)
SIP4-FA2
  rect 1.651x2.8 hole 0.8: 1(1.08,0)
  oval 1.651x2.667 hole 0.8: 2(3.08,0) 3(5.08,0) 4(7.08,0)
SIP6-FA2
  rect 1.651x2.8 hole 0.8: 1(-5,0)
  oval 1.651x2.667 hole 0.8: 2(-3,0) 3(-1,0) 4(1,0) 5(3,0) 6(5,0)
SIP8-FA2
  rect 1.651x2.8 hole 0.8: 1(-5,0)
  oval 1.651x2.667 hole 0.8: 2(-3,0) 3(-1,0) 4(1,0) 5(3,0) 6(5,0) 7(7,0) 8(9,0)
SOP8
  oval 1.905x0.61 smd: 1(0,0) 2(0,-1.27) 3(0,-2.54) 4(0,-3.81) 5(5.74,-3.81) 6(5.74,-2.54) 7(5.74,-1.27) 8(5.74,0)
SOP16
  oval 1.905x0.61 smd: 1(0,0) 2(0,-1.27) 3(0,-2.54) 4(0,-3.81) 5(0,-5.08) 6(0,-6.35) 7(0,-7.62) 8(0,-8.89) 9(5.588,-8.89) 10(5.588,-7.62) 11(5.588,-6.35) 12(5.588,-5.08) 13(5.588,-3.81) 14(5.588,-2.54) 15(5.588,-1.27) 16(5.588,0)
SOT-23-Q
  rect 1.016x1.219 smd: B(-1.016,-1.143) C(0,1.143) E(1.016,-1.143)
SPEAKER
  oval 1.5x2 hole 1.1: 1(-0.254,0) 2(6.754,0)
SW35
  oval 1.778x2.54 hole 1.524: 1(-6.477,0) 5(6.523,0)
  oval 1.778x2.032 hole 1.143: 2(-2.977,0) 3(0.023,0) 4(3.023,0)
TINY6410_2
  rect 1.219x1.219 hole 0.711: A1(3,48) B1(3,4) C1(5,11)
  round 1.219 hole 0.711: A2(3,46) A3(5,48) A4(5,46) A5(7,48) A6(7,46) A7(9,48) A8(9,46) A9(11,48) A10(11,46) A11(13,48) A12(13,46) A13(15,48) A14(15,46) A15(17,48) A16(17,46) A17(19,48) A18(19,46) A19(21,48) A20(21,46) A21(23,48) A22(23,46) A23(25,48) A24(25,46) A25(27,48) A26(27,46) A27(29,48) A28(29,46) A29(31,48) A30(31,46) A31(33,48) A32(33,46) A33(35,48) A34(35,46) A35(37,48) A36(37,46) A37(39,48) A38(39,46) A39(41,48) A40(41,46) A41(43,48) A42(43,46) A43(45,48) A44(45,46) A45(47,48) A46(47,46) A47(49,48) A48(49,46) A49(51,48) A50(51,46) A51(53,48) A52(53,46) A53(55,48) A54(55,46) A55(57,48) A56(57,46) A57(59,48) A58(59,46) A59(61,48) A60(61,46) B2(3,2) B3(5,4) B4(5,2) B5(7,4) B6(7,2) B7(9,4) B8(9,2) B9(11,4) B10(11,2) B11(13,4) B12(13,2) B13(15,4) B14(15,2) B15(17,4) B16(17,2) B17(19,4) B18(19,2) B19(21,4) B20(21,2) B21(23,4) B22(23,2) B23(25,4) B24(25,2) B25(27,4) B26(27,2) B27(29,4) B28(29,2) B29(31,4) B30(31,2) B31(33,4) B32(33,2) B33(35,4) B34(35,2) B35(37,4) B36(37,2) B37(39,4) B38(39,2) B39(41,4) B40(41,2) B41(43,4) B42(43,2) B43(45,4) B44(45,2) B45(47,4) B46(47,2) B47(49,4) B48(49,2) B49(51,4) B50(51,2) B51(53,4) B52(53,2) B53(55,4) B54(55,2) B55(57,4) B56(57,2) B57(59,4) B58(59,2) B59(61,4) B60(61,2) C2(3,11) C3(5,13) C4(3,13) C5(5,15) C6(3,15) C7(5,17) C8(3,17) C9(5,19) C10(3,19) C11(5,21) C12(3,21) C13(5,23) C14(3,23) C15(5,25) C16(3,25) C17(5,27) C18(3,27) C19(5,29) C20(3,29) C21(5,31) C22(3,31) C23(5,33) C24(3,33) C25(5,35) C26(3,35) C27(5,37) C28(3,37) C29(5,39) C30(3,39)
TO-252
  rect 1.194x1.981 smd: 1(0,0) 2(2.261,0) 3(4.521,0)
  rect 5.41x7.01 smd: 4(2.261,6.706)
TVOUT
  oval 3.048x2.54 hole 2.21: 1(0,0) 2(0,9)
  round 3.048 hole 2.032: 3(-4.5,4.5)
USB-A2
  round 1.651 hole 1: 1(0,0) 4(-7,0)
  round 1.524 hole 1: 2(-2.504,0) 3(-4.498,0)
  round 3.81 hole 2: 5(3.084,2.718) 6(-10.074,2.718)
VR3_7X7
  round 1.575 hole 0.9: 1(-1.36,-1) 2(3.64,-1) 3(1.14,2)

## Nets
AGND: C29.2 C30.2 C31.2 C32.2 C33.2 C34.2 C37.2 C38.2 C41.2 C42.1 C43.2 C44.2 C45.2 C46.2 C47.2 C48.2 C57.1 C58.2 C59.1 C60.2 MIC1.2 MIC2.5(E) R46.1 R47.1 R62.1 R63.2 SPK1.5(E) U6.20(SPKGND2) U6.24(SPKGND1) U6.28(AGND)
AVDD_CCD_1.8V: C107.2 L8.2 U9.4(PLL_AVDD) U9.32(CH2_AVDD)
GND: BAT1.2(-) C8.2 C9.2 C10.2 C11.2 C15.2 C16.2 C17.2 C18.2 C19.2 C20.2 C21.1 C22.2 C23.2 C24.2 C25.2 C26.2 C27.2 C28.2 C35.2 C40.1 C49.1 C50.2 C51.2 C52.2 C54.2 C62.1 C64.2 C67.2 C68.2 C73.2 C75.2 C76.2 C77.2 C78.2 C79.2 C80.2 C81.2 C82.2 C83.2 C84.2 C85.2 C86.2 C87.2 C88.2 C89.2 C90.2 C91.2 C92.2 C93.2 C94.2 C95.2 C96.2 C97.2 C105.1 C106.1 C113.1 C142.2 C144.2 C145.2 C148.2 CAMERA.20 CN1.2 CN1.3 COM0.5 COM3.5 CON1.4 CON2.6 CON3.4 CON4.4 CON5.2 CON5.3 CON6.8 CON8.4(GND1) CON8.9(GND2) CON8.15(GND3) CON8.18(GND4) CON8.21(GND5) CON8.26(GND6) CON8.27(GND7) CON8.29(GND8) CON8.34(GND9) CON8.35(GND10) CON8.37(GND11) CON8.40(GND12) CON8.43(GND13) CON8.M1 CON8.M2 CON10.3(GND2) CON10.6(GND1) CON10.12(PAD1) CON10.13(PAD2) H1.1 H2.1 H3.1 H4.1 H5.1 H6.1 H7.1 H8.1 H9.1 H10.1 H11.1 H12.1 H13.1 H14.1 K1.2 K2.2 K3.2 K4.2 K5.2 K6.2 K7.2 K8.2 L9.2 LCD1.11(GND1) LCD1.20(GND2) LCD1.29(GND3) LCD1.37(GND4) LCD1.38(GND5) LCD1.39(GND6) LCD1.40(GND7) LCD1.45(GND8) LCD1.A LCD1.B LCD2.11(GND1) LCD2.20(GND2) LCD2.29(GND3) LCD2.A LCD2.B LCD3.11(GND1) LCD3.20(GND2) LCD3.29(GND3) LCD3.A LCD3.B LCD4.11 LCD4.20 LCD4.29 LCD4.37 LCD4.38 LCD4.39 LCD4.40 LED_3.3.2(CATHODE) MINIUSB1.5(GND) MINIUSB1.6(#6) MINIUSB1.7(#7) MINIUSB1.8(#8) MINIUSB1.9(#9) P1.4(GND) Q2.E(EMITTER) R3.1 R8.2 R16.1 R63.1 R91.2 R93.2 R94.2 R99.2 R109.2 R111.1 R113.2 R115.1 R116.1 R117.1 R121.2 R135.2 R136.2 R139.1 R142.1 RST.2 SDIO.2 SDIO.A SDIO.B TINY210.A2 TINY210.C20 U2.1(GND) U4.5(AGND2) U4.6(AGND3) U4.15(GND) U4.33(GND2) U4.41(TEST) U4.45(GND1) U4.47(AGND1) U4.48(BGGND) U5.1(A0) U5.2(A1) U5.3(A2) U5.4(GND) U5.7(WP) U6.9(DGND) U6.G1(GND_PADDLE) U7.1(RESERVED1) U7.4(AVSS) U7.8(DVSS) U8.15(VSS) U9.19(DGND) U11.11(TEST) U11.37(VSS(FLAG)) USBH1.4(GND1) USBH1.5(GND3) USBH1.6(GND2) USBH2.4(GND1) USBH2.5(GND3) USBH2.6(GND2) USBH3.4(GND1) USBH3.5(GND3) USBH3.6(GND2) W1.1(A)
GND_EARTH: C21.2 LAN1.8(CHS_GND)
VBAT: BAT1.1(+) D1.2(K) R11.1
VDD_3.3V: C10.1 C11.1 C15.1 C16.1 C17.1 C18.1 C27.1 C28.1 C62.2 C67.1 C68.1 C79.1 C142.1 C144.1 C145.1 C148.1 CON6.1 CON8.2(VDD_3V3A) CON8.24(VDD_3V3B) CON8.39(VDD_3V3C) CON8.41(VDD_3V3D) CON8.52(VDD_3V3E) CON10.4(VDD) D1.1(A) D4.1(ANODE) FB1.1 FB2.1 FB5.1 J1.2 R4.1 R5.2 R9.1 R10.1 R12.2 R13.2 R14.2 R18.2 R19.2 R20.1 R21.1 R23.1 R27.1 R28.1 R30.1 R31.2 R32.2 R34.1 R35.2 R37.2 R38.2 R39.2 R40.2 R41.2 R42.2 R43.1 R49.2 R60.1 R64.1 R65.1 R66.1 R71.2 R72.2 R73.2 R74.2 R75.2 R107.2 R108.2 R114.2 R118.2 R119.2 R126.2 R127.2 R128.2 R129.2 R131.2 R132.2 R133.2 R134.2 SDIO.1 U2.2(VOUT) U2.4(TAB) U4.23(VDD1) U4.30(VDD2) U4.42(VDD3) U5.8(VDD) U7.3(AVDD) U7.9(DVDD) U8.16(VDD) W1.2(B)
VDD_5V: BUZZER1.1 C8.1 C9.1 C73.1 C96.1 C97.1 CON1.3 CON2.5 CON3.3 CON4.3 CON5.1 FB3.1 LCD1.1(VDD5V_1) LCD1.2(VDD5V_2) LCD2.1(VDD5V_1) LCD2.2(VDD5V_2) LCD3.1(VDD5V_1) LCD3.2(VDD5V_2) LCD4.1 LCD4.2 S1.2 TINY210.A1 U2.3(VIN) USBH1.1(VBUS) USBH2.1(VBUS) USBH3.1(VBUS)
VDD_AUDIO_A3.3V: C31.1 C32.1 FB2.2 U6.32(AVDD)
VDD_AUDIO_D3.3V: C50.1 C54.1 FB5.2 U6.8(DCVDD) U6.10(DBVDD)
VDD_AUDIO_SPK: C29.1 C30.1 FB1.2 FB3.2 U6.21(SPKVDD2) U6.26(SPKVDD1)
VDD_CAM_1.8V: C106.2 CAMERA.19 L8.1 TINY210.C19 U9.20(DVDD)
VDD_CAM_2.5V: CAMERA.18 TINY210.C18
VDD_CCD_3.3V: C105.2 J1.1 R143.1 R144.2 R145.1 R146.1 U9.10(IO_DVDD)
VDD_CMOS_3.3V: CAMERA.17 J1.3
VDD_IN: CN1.1 CON5.4 S1.3
VDD_RTC_AP: R11.2 TINY210.B4
AUDIO_XI2SCDCLK0: R133.1 TINY210.B30 U6.11(MCLK)
AUDIO_XI2SLRCK0: R131.1 TINY210.B31 U6.13(DACLRC)
AUDIO_XI2SSCLK0: R132.1 TINY210.B29 U6.12(BCLK)
AUDIO_XI2SSDI0: R128.1 TINY210.B33 U6.16(ADCDAT)
AUDIO_XI2SSDO0_0: R129.1 TINY210.B32 U6.14(DATDAT)
CAM_A_RESET: C113.2 CAMERA.4 R146.2 TINY210.C4 U9.8(R\E\S\E\T\B\)
CAM_SCL0: CAMERA.2 R140.1 TINY210.C2
CAM_SDA0: CAMERA.1 R141.1 TINY210.C1
CAMERA_A_GPIO2: CAMERA.3 TINY210.C3
CCD_AGND: AVIN.3(GND) C65.2 C104.2 C107.1 C108.2 C109.2 C111.1 C112.1 L9.1 R51.2 U9.3(PLL_AGND) U9.7(NSUB) U9.31(CH1_AGND)
CCD_SCL: R140.2 R143.2 U9.21(SCL)
CCD_SDA: R141.2 R144.1 U9.22(SDA)
DM2-: R110.1 U11.3(USBDN2_DM)
DM3-: R89.1 U11.6(USBDN3_DM)
DM4-: R95.1 U11.8(USBDN4_DM)
DM9000_RX+: LAN1.3(RX+) R26.1 U4.3(RX+)
DM9000_RX-: LAN1.6(RX-) R29.1 U4.4(RX-)
DM9000_TX+: LAN1.1(TD+) R24.1 U4.7(TX+)
DM9000_TX-: LAN1.2(TD-) R25.1 U4.8(TX-)
DP2+: R112.1 U11.4(USBDN2_DP)
DP3+: R90.1 U11.7(USBDN3_DP)
DP4+: R97.1 U11.9(USBDN4_DP)
EARPHONE_DETECT: C35.1 R49.1 R92.1 SPK1.2(B)
HS_IND/CFG_SEL1: R115.2 R134.1 U11.25(HS_IND/CFG_SEL1)
LANLED: LAN1.11(LEDY-) U4.39(LED1)
LINKLED: LAN1.10(LEDG-) U4.38(LED2)
LOCAL_PWR: R111.2 U11.28(SUSP_IND/LOCAL_PWR/NON_REM0)
M_NRESET: RST.1 TINY210.B3
MICBIAS: C59.2 C60.1 R59.2 U6.1(MICBIAS)
NET_AVDD25: C22.1 C23.1 C24.1 LAN1.4(CT2) LAN1.5(CT1) U4.2(AVDD25_2) U4.9(AVDD25_1)
NRESET: C83.1 R114.1 U11.26(R\E\S\E\T\)
NWAIT: R5.1 TINY210.B41
OM1: R1.2 TINY210.B1
RBIAS: R121.1 U11.35(RBIAS)
RSRXD0: COM0.2 U8.13(RIN1)
RSRXD3: COM3.2 U8.8(RIN2)
RSTXD0: COM0.3 U8.14(T1OUT)
RSTXD3: COM3.3 U8.7(T2OUT)
SCL/CFG_SEL0: R107.1 R116.2 U11.24(SCL/SMBCLK/CFG_SEL0)
SDA: R108.1 R117.2 U11.22(SDA/SMBDATA/NON_REM1)
SPK_OUT_LN: C38.1 CON12.2 U6.23(SPK_LN)
SPK_OUT_LP: C37.1 CON12.1 U6.25(SPK_LP)
SPK_OUT_RN: C48.1 CON12.3 U6.19(SPK_RN)
SPK_OUT_RP: C47.1 CON12.4 U6.22(SPK_RP)
USB_D+: R80.2 U11.2(USBDN1_DP)
USB_D-: R81.2 U11.1(USBDN1_DM)
USIM_CLK: C76.1 CON8.12(USIM_CLK) P1.3(CLK)
USIM_DATA: C77.1 CON8.10(USIM_DATA) P1.6(DATA)
USIM_RST: C78.1 CON8.14(USIM_RESET) P1.2(RST)
USIM_VCC: C75.1 CON8.8(USIM_POWER) P1.1(VCC)
W_DISABLE_N: CON8.20(W_DISABLE_N) R75.1
WIFI0_PD_GPIO: R12.1 SDIO.11 TINY210.A41
WIFI0_RESET_GPIO: R27.2 SDIO.12 TINY210.A42
XADCAIN0: C64.1 CON6.2 TINY210.A39 W1.3(WIPER)
XADCAIN1: CON6.3 TINY210.A40
XADCAIN6_YM: CON6.4 TINY210.A38
XADCAIN7_YP: CON6.5 TINY210.A37
XADCAIN8_XM: CON6.6 TINY210.A36
XADCAIN9_XP: CON6.7 TINY210.A35
XCICLKENB: CAMERA.5 TINY210.C5
XCIHREF: CAMERA.6 R137.2 R138.2 TINY210.C6
XCIPCLK: CAMERA.8 TINY210.C8 U9.9(SCLK)
XCIVSYNC: CAMERA.7 TINY210.C7 U9.24(VSYNC/PALI)
XCIYDATA0: CAMERA.16 TINY210.C16 U9.18(YOUT0)
XCIYDATA1: CAMERA.15 TINY210.C15 U9.17(YOUT1)
XCIYDATA2: CAMERA.14 TINY210.C14 U9.16(YOUT2)
XCIYDATA3: CAMERA.13 TINY210.C13 U9.15(YOUT3)
XCIYDATA4: CAMERA.12 TINY210.C12 U9.14(YOUT4)
XCIYDATA5: CAMERA.11 TINY210.C11 U9.13(YOUT5)
XCIYDATA6: CAMERA.10 TINY210.C10 U9.12(YOUT6)
XCIYDATA7: CAMERA.9 R139.2 TINY210.C9 U9.11(YOUT7/I2CSEL)
XDACOUT: TINY210.A51
XEINT6_SD0_NWP: CON10.10(WP) TINY210.B24
XEINT7: TINY210.B40 U4.34(INT)
XEINT8: TINY210.A30
XEINT9: R28.2 SDIO.16 TINY210.B34
XEINT10: LCD1.31(EINT10) LCD2.31(EINT10) LCD3.31(EINT10) LCD4.31 TINY210.A22
XEINT11: R30.2 TINY210.A46 U7.5(I\N\T\)
XEINT14: LCD1.43(EINT14) LCD4.43 TINY210.C24
XEINT15: LCD1.44(EINT15) LCD4.44 TINY210.C22
XEINT16/KP_COL0: CON7.1 K1.1 R35.1 TINY210.A53
XEINT17/KP_COL1: CON7.2 K2.1 R37.1 TINY210.A54
XEINT18/KP_COL2: CON7.3 K3.1 R39.1 TINY210.A55
XEINT19/KP_COL3: CON7.4 K4.1 R40.1 TINY210.A56
XEINT24/KP_ROW0: CON7.5 K5.1 R43.2 TINY210.A57
XEINT25/KP_ROW1: CON7.6 K6.1 R64.2 TINY210.A58
XEINT26/KP_ROW2: CON7.7 K7.1 R65.2 TINY210.A59
XEINT27/KP_ROW3: CON7.8 K8.1 R66.2 TINY210.A60
XI2CSCL0: R9.2 R31.1 R57.1 R127.1 SDIO.5 TINY210.B19 U5.6(SCL) U7.6(SCL)
XI2CSCL2/IEM_SPWI: LCD1.41(SCL2) LCD4.41 TINY210.C23
XI2CSDA0: R10.2 R32.1 R58.1 R126.1 SDIO.6 TINY210.B20 U5.5(SDA) U7.7(SDA)
XI2CSDA2/IEM_SCLK: LCD1.42(SDA2) LCD4.42 TINY210.C21
XM0ADDR0: TINY210.B35
XM0ADDR1: TINY210.B36
XM0ADDR2: R7.2 TINY210.B37
XM0ADDR3: TINY210.B38
XM0CSN1: TINY210.B39 U4.37(CS#)
XM0DATA0: TINY210.B45 U4.18(SD0)
XM0DATA1: TINY210.B46 U4.17(SD1)
XM0DATA2: TINY210.B47 U4.16(SD2)
XM0DATA3: TINY210.B48 U4.14(SD3)
XM0DATA4: TINY210.B49 U4.13(SD4)
XM0DATA5: TINY210.B50 U4.12(SD5)
XM0DATA6: TINY210.B51 U4.11(SD6)
XM0DATA7: TINY210.B52 U4.10(SD7)
XM0DATA8: TINY210.B53 U4.31(SD8)
XM0DATA9: TINY210.B54 U4.29(SD9)
XM0DATA10: TINY210.B55 U4.28(SD10)
XM0DATA11: TINY210.B56 U4.27(SD11)
XM0DATA12: TINY210.B57 U4.26(SD12)
XM0DATA13: TINY210.B58 U4.25(SD13)
XM0DATA14: TINY210.B59 U4.24(SD14)
XM0DATA15: TINY210.B60 U4.22(SD15)
XM0OEN: TINY210.B44 U4.35(IOR#)
XM0WEN: TINY210.B43 U4.36(IOW#)
XMMC0CDN: CON10.11(NCD) R71.1 TINY210.B23
XMMC0DATA0: CON10.7(DAT0) R73.1 TINY210.B25
XMMC0DATA1: CON10.8(DAT1) R72.1 TINY210.B26
XMMC0DATA2: CON10.9(DAT2) R74.1 TINY210.B27
XMMC0DATA3: CON10.1(CD/DAT3) R38.1 TINY210.B28
XMMC2CDN/SPI_MISO2: R14.1 SDIO.15 TINY210.A45
XMMC2CLK/SPI_CLK2: R13.1 SDIO.13 TINY210.A43
XMMC2CMD/SPI_CSN2: R23.2 SDIO.14 TINY210.A44
XMMC2DATA0/SPI_MOSI2: R18.1 SDIO.17 TINY210.A47
XMMC2DATA1: R34.2 SDIO.18 TINY210.A48
XMMC2DATA2: R19.1 SDIO.19 TINY210.A49
XMMC2DATA3: R60.2 SDIO.20 TINY210.A50
XMMCCLK0: CON10.5(CLK) R41.1 TINY210.B21
XMMCCMD0: CON10.2(CMD) R42.1 TINY210.B22
XNRSTOUT: LCD1.32(NRESET) LCD2.32(NRESET) LCD3.32(NRESET) LCD4.32 TINY210.B42 U4.40(PWRST#)
XPWMTOUT0: R6.2 TINY210.A52
XPWMTOUT1: LCD1.30(TOUT1) LCD2.30(TOUT1) LCD3.30(TOUT1) LCD4.30 TINY210.A26
XSPICKL1: SDIO.9 TINY210.B17
XSPICS1: SDIO.10 TINY210.B18
XSPIMISO1: SDIO.8 TINY210.B16
XSPIMOSI1: SDIO.7 TINY210.B15
XUCTSN1: CON2.2 TINY210.B6
XUHDM: R96.2 TINY210.A32
XUHDP: R82.2 TINY210.A34
XUODM: MINIUSB1.2(D-) TINY210.A31
XUODP: MINIUSB1.3(D+) TINY210.A33
XUODRVVBUS: TINY210.A28
XUOID: MINIUSB1.4(ID) TINY210.A29
XUOVBUS: C51.1 C52.1 MINIUSB1.1(VBUS) TINY210.A27
XURTSN1: CON2.1 TINY210.B5
XURXD0: CON1.2 TINY210.B8 U8.12(ROUT1)
XURXD1: CON2.4 TINY210.B10
XURXD2: CON3.2 SDIO.4 TINY210.B12
XURXD3: CON4.2 TINY210.B14 U8.9(ROUT2)
XUTXD0: CON1.1 TINY210.B7 U8.11(T1IN)
XUTXD1: CON2.3 TINY210.B9
XUTXD2: CON3.1 SDIO.3 TINY210.B11
XUTXD3: CON4.1 TINY210.B13 U8.10(T2IN)
XVHSYNC: LCD1.35(HSYNC) LCD2.35(HSYNC) LCD3.35(HSYNC) LCD4.35 TINY210.A24
XVVCLK: LCD1.36(VCLK) LCD2.36(VCLK) LCD3.36(VCLK) LCD4.36 TINY210.A25
XVVD0: LCD1.3(VD0) LCD2.3(VD0) LCD3.3(VD0) LCD4.3 TINY210.C25
XVVD1: LCD1.4(VD1) LCD2.4(VD1) LCD3.4(VD1) LCD4.4 TINY210.C26
XVVD2: LCD1.5(VD2) LCD2.5(VD2) LCD3.5(VD2) LCD4.5 TINY210.A20
XVVD3: LCD1.6(VD3) LCD2.6(VD3) LCD3.6(VD3) LCD4.6 TINY210.A19
XVVD4: LCD1.7(VD4) LCD2.7(VD4) LCD3.7(VD4) LCD4.7 TINY210.A18
XVVD5: LCD1.8(VD5) LCD2.8(VD5) LCD3.8(VD5) LCD4.8 TINY210.A17
XVVD6: LCD1.9(VD6) LCD2.9(VD6) LCD3.9(VD6) LCD4.9 TINY210.A16
XVVD7: LCD1.10(VD7) LCD2.10(VD7) LCD3.10(VD7) LCD4.10 TINY210.A15
XVVD8: LCD1.12(VD8) LCD2.12(VD8) LCD3.12(VD8) LCD4.12 TINY210.C27
XVVD9: LCD1.13(VD9) LCD2.13(VD9) LCD3.13(VD9) LCD4.13 TINY210.C28
XVVD10: LCD1.14(VD10) LCD2.14(VD10) LCD3.14(VD10) LCD4.14 TINY210.A14
XVVD11: LCD1.15(VD11) LCD2.15(VD11) LCD3.15(VD11) LCD4.15 TINY210.A13
XVVD12: LCD1.16(VD12) LCD2.16(VD12) LCD3.16(VD12) LCD4.16 TINY210.A12
XVVD13: LCD1.17(VD13) LCD2.17(VD13) LCD3.17(VD13) LCD4.17 TINY210.A11
XVVD14: LCD1.18(VD14) LCD2.18(VD14) LCD3.18(VD14) LCD4.18 TINY210.A10
XVVD15: LCD1.19(VD15) LCD2.19(VD15) LCD3.19(VD15) LCD4.19 TINY210.A9
XVVD16: LCD1.21(VD16) LCD2.21(VD16) LCD3.21(VD16) LCD4.21 TINY210.C29
XVVD17: LCD1.22(VD17) LCD2.22(VD17) LCD3.22(VD17) LCD4.22 TINY210.C30
XVVD18: LCD1.23(VD18) LCD2.23(VD18) LCD3.23(VD18) LCD4.23 TINY210.A8
XVVD19: LCD1.24(VD19) LCD2.24(VD19) LCD3.24(VD19) LCD4.24 TINY210.A7
XVVD20: LCD1.25(VD20) LCD2.25(VD20) LCD3.25(VD20) LCD4.25 TINY210.A6
XVVD21: LCD1.26(VD21) LCD2.26(VD21) LCD3.26(VD21) LCD4.26 TINY210.A5
XVVD22: LCD1.27(VD22) LCD2.27(VD22) LCD3.27(VD22) LCD4.27 TINY210.A4
XVVD23: LCD1.28(VD23) LCD2.28(VD23) LCD3.28(VD23) LCD4.28 TINY210.A3
XVVDEN: LCD1.33(VDEN) LCD2.33(VDEN) LCD3.33(VDEN) LCD4.33 TINY210.A21
XVVSYNC: LCD1.34(VSYNC) LCD2.34(VSYNC) LCD3.34(VSYNC) LCD4.34 TINY210.A23
N490506: R57.2 U6.17(SCLK)
N490846: R58.2 U6.18(SDIN)
N563338: C46.1 U6.6(RINPUT2)
N563659: C45.1 U6.7(RINPUT3/JD3)
N565258: C44.1 U6.2(LINPUT3/JD2)
N570115: C43.1 U6.5(RINPUT1)
N579751: C36.2 U6.4(LINPUT1)
N580413: C36.1 C41.1 R59.1 R62.2 R67.2
N605417: C34.1 C55.2 R46.2 SPK1.3(C) SPK1.4(D)
N617320: C33.1 C56.2 R47.2 SPK1.1(A)
N3676300: R1.1 R2.2 S2.3
N3676952: R2.1 TINY210.B2
N3684154: R3.2 S2.4
N3805887: LED_3.3.1(ANODE) R4.2
N3869369: R7.1 U4.32(CMD)
N3921053: C19.1 U4.43(X2) Y1.1
N3921204: C20.1 U4.44(X1) Y1.2
N3925254: R8.1 U4.1(BGRES)
N3968686: C25.1 R24.2 R25.2
N3970814: C26.1 R26.2 R29.2
N3982722: LAN1.9(LEDG+) R20.2
N3983324: LAN1.12(LEDY+) R21.2
N4027687: Q2.B(BASE) R6.1 R16.2
N4771984: C42.2 U6.3(LINPUT2)
N5234173: R92.2 U6.15(ADCLRC/GPIO1)
N5390728: C55.1 U6.31(HP_L)
N5390947: C56.1 U6.29(HP_R)
N5424123: C57.2 C58.1 U6.27(VMID)
N6095373: C39.2 U8.1(C1+)
N6095738: C39.1 U8.3(C1-)
N6103030: C40.2 U8.2(V+)
N6103395: C49.2 U8.6(V-)
N6105619: C61.1 U8.4(C2+)
N6105986: C61.2 U8.5(C2-)
N6195963: BUZZER1.2 Q2.C(COLLECTOR)
N9607388: R96.1 R136.1 U11.30(USBUP_DM)
N9607392: R82.1 R135.1 U11.31(USBUP_DP)
N9607432: C95.1 R130.2 U11.33(XTAL1/CLKIN) Y3.2
N9607572: C80.1 C82.1 C86.1 C87.1 C88.1 C89.1 C93.1 C94.1 R118.1 U11.5(VDDA33#5) U11.10(VDDA33#10) U11.15(VDD33(REG)) U11.23(VDD33(IO)) U11.29(VDDA33#29) U11.36(VDDPLLREF/VDDA33)
N9607910: C81.1 R130.1 U11.32(XTAL2/CLKIN_EN) Y3.1
N9607998: C85.1 R119.1 U11.27(VBUS_DET)
N9608162: C84.1 C90.1 U11.34(PLLFILT)
N9608206: C91.1 C92.1 U11.14(CRFILT)
N9608680: R89.2 R91.1 USBH1.2(D-)
N9608700: R90.2 R93.1 USBH1.3(D+)
N9608868: R94.1 R95.2 USBH2.2(D-)
N9608880: R97.2 R99.1 USBH2.3(D+)
N9609084: R109.1 R110.2 USBH3.2(D-)
N9609088: R112.2 R113.1 USBH3.3(D+)
N9616349: CON8.36(USB_DM) R81.1
N9616353: CON8.38(USB_DP) R80.1
N9617073: CON8.22(PERST_N) PERST_N.1
N9617077: CON8.42(LED_WWAN_N) R76.1
N9617165: D4.2(CATHODE) R76.2
N9621622: AVIN.1(OUT) AVIN.2(~) C104.1 L6.1
N9621696: R142.2 R145.2 U9.28(PDN)
N9622060: C53.2 U9.1(AIP1A)
N9622080: C63.2 U9.2(AIP1B)
N9622122: C53.1 C63.1 C65.1 L6.2 R51.1
N9622404: C109.1 U9.5(XTAL/OSC) Y2.1
N9622412: C108.1 U9.6(XTAL2) Y2.2
N9622484: C110.2 C112.2 U9.30(REFM)
N9622488: C110.1 C111.2 U9.29(REFP)
N9622590: R137.1 U9.26(AVID)
N9622630: R138.1 U9.25(HSYNC)
N9633247: MIC2.1(A) MIC2.4(D) R67.1
N9633353: MIC1.1 MIC2.2(B) MIC2.3(C)

Pads without a net: BAT1 3 4; COM0 1 4 6 7 8 9 10 11; COM3 1 4 6 7 8 9 10 11; CON8 1 3 5 6 7 11 13 16 17 19 23 25 28 30 31 32 33 44 45 46 47 48 49 50 51; K1 3; K2 3; K3 3; K4 3; K5 3; K6 3; K7 3; K8 3; LAN1 7 M3 M4; LCD2 37 38 39 40; LCD3 37 38 39 40; P1 5; RST 3; S1 1 4 5; S2 1 2 5; TINY210 C17; U4 19 20 21 46; U6 30; U7 2 10 M1 M2; U9 23 27; U11 12 13 16 17 18 19 20 21

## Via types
v1: diameter 0.711, hole 0.356, TOP to BOTTOM, 1274 vias
v2: diameter 1.016, hole 0.711, TOP to BOTTOM, 6 vias

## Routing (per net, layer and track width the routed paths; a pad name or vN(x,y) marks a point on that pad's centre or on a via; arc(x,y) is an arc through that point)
AGND: length 97.9
  TOP w0.305: U6.28 140.08,30.1 C33.2 ; v1(137.16,31.88) 137.82,32.54 U6.24 ; U6.20 136.78,34.54 v1(136.47,34.85)
  TOP w0.508: C33.2 139.83,28.32 v1(140.05,28.32)
  TOP w0.559: v1(135.38,23.88) 135.25,23.75 132.33,23.75 130.81,25.27 130.81,30.78 132.59,32.56 v1(132.59,33.4) ; C45.2 v1(147.96,36.83) C46.2 ; R63.2 132.21,35.43 v1(132.72,35.94) 132.84,35.81 C48.2 ; R63.2 131.6,35.66 130.94,36.32 v1(130.94,36.4) ; R63.2 131.6,34.95 v1(131.06,34.42) 131.06,34.29 130.64,33.86 130.64,33 129.16,31.52 129.16,19.81 130.56,18.41 134.11,18.41 135,19.3 v1(138.18,19.3) ; v1(138.94,24) 138.4,24.54 R47.1 ; C57.1 136.78,26.67 v1(137.29,26.16) ; C59.1 150.55,31.32 C32.2 150.55,28.88 v1(149.99,28.32) ; C37.2 133.86,29.83 v1(133.97,29.72) ; R46.1 141.45,25.12 140.84,24.51 v1(140.84,24) ; v1(145.09,28.38) 145.09,27.36 C34.2 144.27,27.81 144.27,27.94 144.11,28.11 v1(144.11,28.19) 144.11,28.28 144.15,28.32 144.15,29.21 C31.2 ; C29.2 134.37,26.16 v1(134.11,25.91) 133.6,25.91 132.84,26.67 C30.2 ; C41.2 v1(149.48,24.51) ; 137.67,27.56 137.67,27.05 v1(138.3,26.42) ; v1(132.59,33.4) 133.1,33.91 C47.2 ; v1(132.59,33.4) 133.35,32.64 C38.2 ; C44.2 v1(148.17,33.02) ; v1(146.81,28.96) 146.71,29.05 146.71,29.2 146.65,29.26 146.65,29.42 146.56,29.51 C60.2 ; C42.1 148.97,35.31 v1(148.08,35.31) 147.07,35.31 C43.2 ; v1(147.57,24.26) 147.96,24.64 R62.1
  BOTTOM w0.559: SPK1.5 137.42,3.37 ; SPK1.5 134.05,3.37 ; SPK1.5 135.74,1.84 ; SPK1.5 135.74,4.9 ; 142.69,3.37 MIC2.5 ; MIC2.5 146.05,3.37 ; MIC2.5 144.37,1.84 ; MIC2.5 144.37,4.9 ; MIC1.2 146.02,22.41 ; MIC1.2 147.09,21.34 ; MIC1.2 146.02,20.27
  vias: v1(131.44,14.86) v1(135.89,12.95) v1(138.81,14.22) v1(145.8,12.06)
AVDD_CCD_1.8V: length 19.1
  TOP w0.254: U9.4 152.78,102.37 152.4,102.74 v1(152.4,102.74) ; 153.16,98.17 152.78,98.17 152.37,98.58 U9.32 152.37,100.71
  TOP w0.406: 153.16,98.17 155.32,98.17 C107.2
  TOP w0.559: v1(152.4,102.74) 152.4,100.74 152.37,100.71 ; L8.2 145.29,102.87 v1(145.8,103.38)
  BOTTOM w0.559: v1(152.4,102.74) 146.43,102.74 v1(145.8,103.38)
GND: length 1879.9
  TOP w0.203: 122.56,45.97 123.65,45.97 v1(123.8,46.13) ; 133.99,47.5 133.99,46.61 ; 152.02,46.48 152.02,47.5 ; 153.92,45.97 153.92,47.37 154.05,47.5 ; 131.34,48.01 130.3,48.01 130.05,47.75 ; 136.02,45.47 136.02,44.45 ; 120.47,59.05 121.69,59.05 ; 138.05,45.47 138.05,44.32 ; 168.02,46.48 168.02,47.5 ; 118.44,59.03 119.48,59.03 ; 168.02,45.47 168.02,44.58 ; 136.02,46.61 136.02,47.75 ; 8.99,55.83 9.98,55.83 10.19,56.03 v1(10.49,56.03) 10.59,55.93 12.42,55.93 12.52,56.03 ; 154.05,45.59 154.05,44.32 ; 137.92,89.41 137.92,88.52 ; 133.99,45.47 133.99,44.58 ; 138.05,46.61 138.05,47.5 ; 138.05,91.44 137.92,91.31 137.92,90.55 ; 144.02,89.66 144.02,88.52 ; 152.02,45.47 152.02,44.2 152.15,44.07 ; 147.96,45.59 v1(147.96,44.2) ; 145.92,89.41 145.92,88.39
  TOP w0.254: U7.8 62.74,79.25 v1(63.12,79.63) ; v1(126.63,99.5) 126.15,99.5 125.88,99.77 121.69,99.77 ; v1(89.28,111.76) 90.78,113.26 U11.11 90.78,115.69 90.47,116 ; 92.08,123.55 93.24,123.55 ; v1(152.4,48.51) 152.02,48.13 152.02,47.5 ; 129.29,48.11 129.69,48.11 130.05,47.75 ; U7.4 v1(62.24,80.01) ; U7.1 63.74,82.31 63.63,82.42 v1(63.5,82.42) ; 83.72,123.67 83.72,125.12 ; U4.15 172.62,30.63 v1(173.23,31.24) ; U4.33 166.26,35.33 v1(166.24,35.31) ; U4.5 166.76,27.17 v1(167.03,26.9) 167.26,27.13 U4.6 ; 96.04,123.52 97.16,123.52 ; U4.41 v1(164.45,33.14) ; U4.47 v1(164.56,30.14) 164.06,29.63 U4.48 v1(161.75,29.63) ; 86.21,123.57 87.27,123.57 ; U4.45 v1(164.59,31.14) ; 154.05,47.5 154.05,47.62 154.24,47.82 ; 81.89,123.67 81.97,123.6 83.29,123.6 83.36,123.67 ; 94.16,123.55 95.25,123.55 ; 132,48.01 132.06,47.95 132.06,46.61 132.08,46.59 v1(132.08,45.97) 132.08,45.41 132.06,45.39 132.06,43.92 131.06,42.93 ; 132,48.01 131.34,48.01 ; 132,48.01 133.48,48.01 133.99,47.5 ; 84.12,123.57 85.32,123.57 ; v1(148.72,104.27) 148.72,103.89 148.2,103.37 U9.19 ; 88.11,123.57 89.15,123.57 ; v1(140.34,34.29) v1(141.6,35.56) 142.07,36.03 142.07,36.22 ; 89.66,122.15 88.8,121.28 v1(88.52,121.28) ; 152.02,45.97 152.02,46.48 ; 90.14,123.6 91.19,123.6
  TOP w0.279: 125.98,47.6 v1(125.98,46.35) 125.98,44.2 ; 123.93,46 135.13,46 135.23,45.9 135.25,45.9 ; v1(89.89,77.14) 90.05,76.98 LCD2.29 ; LCD2.20 89.95,72.48 v1(89.79,72.64)
  TOP w0.305: 87.66,124.08 87.66,125.48 ; 130.05,47.75 130.05,47.41 130.03,47.4 130.03,44.08 130.3,43.81 ; v1(95.5,68.14) 95.34,67.98 LCD2.11 ; 164.08,90.42 164.08,91.82 ; 87.66,123.57 87.66,121.79 ; 91.66,123.57 91.66,121.79 ; 121.92,45.59 121.92,44.2 ; 166.02,89.66 166.02,88.14 ; 122.05,47.75 121.92,47.62 121.92,46.23 ; 85.66,124.08 85.66,125.48 ; 142.07,36.22 142.09,36.23 U6.9 ; 162.12,88.14 161.93,88.33 161.93,89.47 162.12,89.66 ; 168.02,89.66 168.02,88.14 ; 128.14,43.94 127.97,44.12 127.97,45.4 127.91,45.46 v1(127.91,46.13) 127.91,46.54 127.97,46.6 127.97,47.7 128.02,47.75 ; 164.12,88.14 163.96,88.3 163.96,89.5 164.12,89.66 ; 161.93,44.32 161.93,46.02 v1(161.85,46.1) ; 95.66,124.08 95.66,125.48 ; 157.99,91.82 157.99,90.17 ; 93.66,123.57 93.66,121.48 v1(93.47,121.28) ; 160.08,90.42 160.08,91.82 ; 97.66,123.57 97.66,121.79 ; 93.66,124.08 93.66,125.48 ; 91.66,124.08 91.66,125.48 ; v1(123.8,46.13) 123.49,46.13 ; v1(123.8,46.13) 123.97,45.96 123.97,44.6 123.95,44.59 123.95,44.2 ; v1(123.8,46.13) 123.8,46.43 123.97,46.6 123.97,47.4 123.95,47.41 123.95,47.75 ; 162.08,90.42 162.08,91.82 ; 157.99,89.66 157.99,88.27 ; 85.66,123.57 85.66,121.79 ; 165.99,90.42 165.99,91.82 ; 89.66,123.57 89.66,122.15 ; 160.12,89.66 160.12,89.41 160.09,89.38 160.09,88.62 160.12,88.59 160.12,88.14 ; 95.66,123.57 95.66,121.79 ; 89.66,124.08 89.66,125.48 ; 97.66,124.08 97.66,125.48 ; 120.27,74.93 121.79,74.93
  TOP w0.559: USBH3.4 123.97,14.09 ; USBH3.4 125.23,12.83 ; USBH3.4 122.71,12.83 ; USBH3.4 123.97,11.57 ; v1(146.05,110.49) 146.05,110.62 146.81,111.38 R94.2 ; K2.2 3.83,94.26 ; K2.2 2.77,93.2 ; K2.2 4.9,93.2 ; K2.2 3.83,92.13 ; 39.65,75.59 39.65,75.59 39.65,73.99 ; 39.65,75.59 v1(40.01,75.95) 40.45,75.51 ; 39.65,75.59 CON8.35 ; v1(85.99,118.24) 86.12,118.36 86.34,118.36 86.97,119 C87.2 C91.2 88.64,119 v1(89.66,120.02) 90.05,119.63 C92.2 C88.2 ; 1.07,111 H8.1 ; H8.1 6.93,111 ; H8.1 4,113.93 ; H8.1 1.78,108.78 v1(1.78,108.46) 1.78,108.22 H7.1 ; R136.2 87,104.23 v1(86.74,103.97) ; 124.46,124.97 C64.2 125.35,125.86 ; C18.2 v1(157.48,35.31) ; K3.2 3.83,87.91 ; K3.2 4.9,86.85 ; K3.2 2.77,86.85 ; K3.2 3.83,85.78 ; 1.07,26 H5.1 ; H5.1 4,23.07 ; H5.1 6.93,26 ; H5.1 4,28.93 ; BAT1.2 86.87,38.25 ; BAT1.2 84.4,36.58 ; BAT1.2 89.33,36.58 ; BAT1.2 86.87,34.9 ; K5.2 4.9,74.15 ; K5.2 2.77,74.15 ; K5.2 3.83,75.21 ; K5.2 3.83,73.08 ; 129.93,35.43 129.54,35.04 v1(129.54,34.16) ; 129.93,35.43 R63.1 130.02,35.59 v1(129.03,36.58) ; 129.93,35.43 v1(128.78,35.43) ; C85.2 v1(81.41,107.57) ; SDIO.A 76.53,126.78 ; SDIO.A 70.66,126.78 ; SDIO.A 73.59,123.85 ; 126,23.07 H12.1 ; H12.1 126,28.93 ; H12.1 123.07,26 ; U5.3 v1(94.74,42.55) ; v1(113.54,75.44) 112.14,74.04 v1(110.59,74.04) v1(107.06,74.04) ; CON8.M1 21.59,74.62 ; CON8.M1 20,72.58 ; CON8.M1 20,75.24 20,75.24 ; v1(150.93,113.74) C96.2 v1(152.27,112.39) ; C68.2 45.47,25.65 43.05,25.65 ; C68.2 45.85,24.38 ; C68.2 44.96,25.27 ; C68.2 v1(47.12,25.27) ; 85.89,17.41 CON1.4 ; CON1.4 84.63,19.18 ; CON1.4 85.89,20.94 ; 3.83,66.73 K6.2 ; K6.2 3.83,68.86 ; K6.2 4.9,67.8 ; K6.2 2.77,67.8 ; 103.07,106 H13.1 ; H13.1 106,108.93 ; H13.1 108.93,106 ; v1(174.04,114.38) C73.2 v1(174.04,117.04) ; 59.47,17.41 CON3.4 ; CON3.4 59.47,20.94 ; CON3.4 58.21,19.18 ; 176,123.07 H3.1 ; H3.1 176,128.93 ; H3.1 173.07,126 ; H3.1 178.93,126 ; CON2.6 70.69,20.94 ; CON2.6 69.44,19.18 ; CON2.6 70.69,17.41 ; v1(161.16,26.67) 160.29,25.8 C22.2 159.11,25.8 v1(158.62,26.29) ; 36.45,75.56 v1(36.83,75.95) 37.25,75.53 CON8.29 ; 36.45,75.56 36.45,75.56 36.45,73.99 ; 36.45,75.56 CON8.27 ; CON8.M2 48.09,75.82 v1(47.5,75.82) ; CON8.M2 49.3,76.65 ; CON8.M2 48.09,73.41 v1(47.5,73.41) ; CON8.M2 47.71,74.62 ; CON8.M2 50.89,74.62 ; 176.25,32 RST.2 177.32,30.94 ; 10.88,12.1 CN1.2 ; CN1.2 13.52,12.1 ; CN1.2 12.2,13.53 ; CN1.2 12.2,10.68 ; 11.42,27.56 11.41,27.56 v1(9.27,27.56) ; 11.42,27.56 v1(11.42,30.08) 11.42,33.41 H9.1 ; 11.42,27.56 v1(13.59,27.56) ; 11.42,27.56 v1(11.42,25.27) ; C9.2 v1(21.08,26.42) ; C9.2 22.61,25.53 ; C9.2 23.5,26.42 ; Q2.E 17.53,98.21 ; Q2.E 16.59,97.17 ; Q2.E 18.47,97.17 ; U5.4 96.75,40.77 ; U5.4 96.01,39.38 ; U5.4 v1(96.01,42.55) ; v1(113.54,79.19) 111.19,76.83 v1(110.59,76.83) v1(107.06,76.83) ; R135.2 v1(89.03,103.92) ; 3.83,60.38 K7.2 ; K7.2 3.83,62.51 ; K7.2 2.77,61.45 ; K7.2 4.9,61.45 ; 2.77,99.55 K1.2 ; K1.2 4.9,99.55 ; K1.2 3.83,100.61 ; K1.2 3.83,98.48 ; 99.18,1.56 MINIUSB1.8 ; MINIUSB1.8 98,3.04 ; MINIUSB1.8 99.18,4.53 ; MINIUSB1.8 100.37,3.04 ; C11.2 34.93,30.99 ; C11.2 34.04,31.88 ; C11.2 34.04,29.59 C40.1 33.78,28.57 33.78,28.57 33.53,28.32 33.53,28.32 33.27,28.07 v1(33.27,27.94) ; v1(26.92,29.59) 26.92,30.3 C10.2 ; 135.67,119.69 USBH2.6 ; USBH2.6 138.01,122.02 ; USBH2.6 140.35,119.69 ; USBH2.6 138.01,117.35 ; 90.65,83.28 LCD2.B ; LCD2.B 88.95,85.24 ; LCD2.B v1(92.99,85.24) v1(96.09,85.24) 97.3,85.24 v1(101.1,89.04) v1(102.43,90.36) 104.47,92.41 105.85,92.41 v1(106,92.25) 106.18,92.08 v1(109.86,92.08) 112.47,92.08 112.8,92.41 114.25,92.41 114.68,92.84 115.57,93.73 117.2,93.73 v1(117.25,93.77) 117.29,93.73 119.99,93.73 v1(120.03,93.77) 119.99,93.77 ; 1.07,106 H7.1 ; H7.1 6.93,106 ; H7.1 4,103.07 ; 92.2,39.38 U5.1 ; U5.1 91.47,40.77 ; U5.1 v1(92.2,42.55) ; 103.07,26 H6.1 ; H6.1 106,28.93 ; H6.1 108.93,26 ; H6.1 106,23.07 ; v1(162.69,22.1) 161.78,23 C24.2 ; v1(21.84,73.28) 20.7,73.28 20,73.98 20,75.24 ; 2.77,80.5 K4.2 ; K4.2 4.9,80.5 ; K4.2 3.83,79.43 ; K4.2 3.83,81.56 ; 157.61,116.97 USBH1.4 ; USBH1.4 158.86,115.71 ; USBH1.4 160.12,116.97 ; USBH1.4 158.86,118.23 ; 4,123.07 H2.1 ; H2.1 4,128.93 ; H2.1 6.93,126 ; H2.1 1.07,126 ; 40.45,75.51 40.45,75.5 CON8.37 ; 40.45,75.51 40.45,73.99 ; 26.05,73.99 v1(26.05,75.69) 26.05,75.69 CON8.9 ; C62.1 v1(65.66,77.47) ; MINIUSB1.5 105.23,10.58 ; MINIUSB1.5 105.92,9.09 ; MINIUSB1.5 105.23,7.61 ; R99.2 141.88,111.48 v1(141.1,112.27) ; v1(118.11,19.94) 118.11,19.94 R109.2 ; v1(147.57,55.5) v1(146.05,55.5) v1(144.53,55.5) v1(141.22,55.5) v1(139.7,55.5) v1(137.67,55.5) ; MINIUSB1.7 99.18,10.18 ; MINIUSB1.7 99.18,7.21 ; MINIUSB1.7 100.37,8.69 ; MINIUSB1.7 98,8.69 ; 26.24,29.92 C10.2 ; C10.2 26.24,32.05 ; C10.2 24.89,30.99 v1(24.77,30.86) ; R93.2 158.52,111.48 v1(157.99,112.01) ; 20,75.24 20.57,75.82 v1(21.84,75.82) ; R3.1 175.26,28.81 174.65,29.42 v1(174.65,29.47) ; v1(28.45,75.69) 28.45,75.69 CON8.15 ; C49.1 35.31,17.53 ; C49.1 33.53,17.53 ; C49.1 34.42,16.64 ; 173.61,112.15 L9.2 ; L9.2 174.51,113.03 ; L9.2 173.61,113.91 ; 139.83,116.97 USBH2.4 ; USBH2.4 141.08,115.71 ; USBH2.4 141.08,118.23 ; USBH2.4 142.34,116.97 ; CON8.4 24.05,84.75 v1(24.26,84.96) ; CON8.43 42.85,75.61 ; 42.85,75.61 v1(43.05,75.82) ; 42.85,75.61 42.85,75.61 42.85,73.99 ; R142.1 150.5,94.87 v1(151.26,94.11) ; v1(116.59,59.82) 104.78,59.82 v1(103.25,58.29) ; C20.2 v1(157.62,31.51) ; LCD4.37 LCD4.38 8.53,90.88 ; C80.2 v1(81.02,117.09) ; 34.05,73.99 v1(34.05,75.95) 34.05,75.94 CON8.21 ; 154.24,47.82 154.94,48.51 v1(155.32,48.51) ; LCD2.A 89.17,60.22 v1(88.65,59.69) ; LCD2.A 92.34,60.22 ; LCD2.A 90.63,62.17 ; R8.2 v1(156.72,23.56) ; C79.2 v1(56.13,83.44) ; 11.07,106 H10.1 ; H10.1 16.93,106 ; H10.1 14,103.07 ; H10.1 14,108.93 ; 173.07,4 H4.1 ; H4.1 178.93,4 ; H4.1 176,1.07 ; H4.1 176,6.93 ; 106.9,3.04 MINIUSB1.9 ; MINIUSB1.9 109.27,3.04 ; MINIUSB1.9 108.08,1.56 ; MINIUSB1.9 108.08,4.53 ; 123.07,111 H14.1 128.93,111 ; R139.1 v1(141.48,107.19) ; 129.67,42.93 131.06,42.93 ; v1(38.99,85.09) 39.25,84.83 39.25,84.2 39.25,84.2 CON8.34 ; 156.59,109.73 157.35,108.97 C113.1 157.99,108.84 v1(158.37,108.46) ; 47.04,19.18 CON4.4 48.29,20.94 ; R121.2 v1(94.24,100.2) ; C84.2 C90.2 94.36,104.27 v1(94.11,104.01) ; USBH1.5 171.29,119.69 ; USBH1.5 168.95,117.35 ; USBH1.5 166.61,119.69 ; USBH1.5 168.95,122.02 ; H1.1 6.93,4 ; H1.1 4,1.07 ; H1.1 4,6.93 ; H1.1 1.07,4 ; C19.2 v1(157.49,33.54) ; 151.17,117.35 USBH2.5 ; USBH2.5 151.17,122.02 ; USBH2.5 148.83,119.69 ; C86.2 98.57,111.89 99.08,111.38 v1(101.09,111.38) ; 101.74,124.55 CAMERA.20 100.67,125.61 ; C95.2 v1(92.71,100.08) ; U2.1 30.48,29.36 ; U2.1 31.51,27.94 ; U2.1 v1(30.48,26.04) ; v1(146.94,42.16) 146.56,41.78 C50.2 ; v1(34.16,86.61) 32.85,85.3 32.85,84.45 32.85,84.45 CON8.18 ; v1(101.6,64.01) v1(107.06,64.01) 108.46,64.01 110.49,66.04 v1(110.59,66.04) 113.94,66.04 v1(114.81,66.9) ; 111.55,10.11 USBH3.5 ; USBH3.5 113.89,7.77 ; USBH3.5 113.89,12.45 ; USBH3.5 116.22,10.11 ; 10.7,7.68 CN1.3 ; CN1.3 12.02,9.1 ; CN1.3 10.7,10.53 ; CN1.3 9.38,9.1 ; C16.2 v1(175.01,39.37) ; C16.2 174.12,37.97 ; C16.2 175.9,37.97 ; v1(153.16,105.54) 153.16,105.16 152.27,104.27 v1(151.38,104.27) ; 9.84,27.18 C8.2 ; C8.2 11.54,25.22 ; C8.2 11.54,29.14 ; C8.2 13.25,27.18 ; 123.56,18.7 R113.2 122.68,19.6 ; CON6.8 122.03,124.45 ; CON6.8 123.29,122.68 ; CON6.8 122.03,120.92 ; v1(101.47,78.23) 101.47,78.31 103.17,80.01 v1(105.66,80.01) 110.08,80.01 v1(110.59,80.52) ; C82.2 85.47,104.02 v1(85.34,103.89) ; K8.2 3.83,56.16 ; K8.2 3.83,54.03 ; K8.2 4.9,55.1 ; K8.2 2.77,55.1 ; TINY210.A2 116.81,89 114.77,86.96 111.72,86.96 v1(110.63,85.86) 109.47,84.71 v1(106.93,84.71) ; 100.2,18.29 C52.2 101.09,19.18 ; LED_3.3.2 v1(22.65,3.64) ; LED_3.3.2 21.35,2.51 ; LED_3.3.2 20.28,3.64 ; 12.5,92.35 11.97,92.88 LCD4.39 ; 108.08,7.21 MINIUSB1.6 ; MINIUSB1.6 109.27,8.69 ; MINIUSB1.6 108.08,10.18 ; MINIUSB1.6 106.9,8.69 ; v1(29.34,113.16) 29.84,112.65 29.84,109.73 ; 82.04,118.11 C89.2 ; C89.2 82.04,119.89 ; C89.2 v1(81.16,119) ; C23.2 v1(171.69,22.37) ; 115.14,19.23 C97.2 116.21,20.3 ; v1(154.18,107.7) 154.18,108.46 C105.1 ; C35.2 v1(126.62,20.07) ; 14.23,18.72 CON5.3 15.42,17.53 ; 15.57,17.53 CON5.2 ; CON5.2 16.77,18.72 ; CON5.2 16.77,16.33 ; 158.95,36.53 C15.2 ; C15.2 v1(157.61,37.59) ; C15.2 158.95,38.66 ; v1(169.57,26.14) 170.16,25.54 C25.2 ; COM0.5 84.34,10.29 ; COM0.5 83.09,11.55 ; COM0.5 83.09,9.03 ; COM0.5 81.83,10.29 ; C81.2 v1(90.55,100.08) ; U5.7 v1(93.47,48.39) ; v1(41.65,85.09) 41.65,85.09 CON8.40 ; U5.2 v1(93.47,42.55) ; C21.1 173.26,24.99 174.12,24.13 v1(174.18,24.13) ; R16.1 v1(18.67,95.25) ; v1(81.89,88.24) 85.85,92.2 v1(88.9,92.2) v1(93.34,92.2) 96.39,92.2 v1(98.12,93.93) 101.6,97.41 v1(105.97,97.41) v1(109.96,97.41) 112.14,97.41 114.3,99.57 v1(119.13,99.57) ; C26.2 163.18,25.74 v1(163.55,26.11) ; R111.1 v1(81.38,106.04) ; v1(96.77,107.44) 96.77,108.33 96.14,108.96 C94.2 ; 11.07,36 H9.1 ; H9.1 14,33.07 ; H9.1 16.93,36 ; 8.63,72.88 LCD4.20 9.59,73.01 10.19,73.61 ; 101.83,21.08 C51.2 100.76,22.15 ; USBH3.6 127.04,12.45 ; USBH3.6 127.04,7.77 ; USBH3.6 124.71,10.11 ; C93.2 v1(81.41,113.66) ; W1.1 128.89,122.19 ; W1.1 127.67,120.97 ; W1.1 126.46,122.19 ; W1.1 127.67,123.41 ; R117.1 v1(81.38,115.19) ; H11.1 108.93,36 ; H11.1 103.07,36 ; H11.1 106,33.07 ; H11.1 106,38.93 ; C106.1 v1(141.48,101.22) ; v1(103.89,82.32) v1(109.35,82.32) 111.28,82.32 113.54,84.58 113.16,84.58 v1(112.59,84.01) ; v1(36.45,85.09) 36.06,84.7 36.05,84.7 36.05,84.7 CON8.26 ; v1(10.29,93.85) 9.59,93.15 LCD4.40 ; 167.77,41.27 C17.2 168.66,42.16 ; C83.2 v1(81.41,109.09) ; v1(61.54,73.48) C67.2 v1(64.44,73.48) ; C54.2 148.51,40.94 v1(149.48,41.91) ; 45.63,10.29 COM3.5 ; COM3.5 46.89,11.55 ; COM3.5 46.89,9.03 ; COM3.5 48.15,10.29 ; LCD4.11 12.8,64.88 ; SDIO.B 58.53,126.78 ; SDIO.B 55.59,123.85 ; SDIO.B 52.66,126.78 ; USBH1.6 158.13,119.69 ; USBH1.6 155.79,122.02 ; USBH1.6 155.79,117.35 ; R91.2 v1(163.71,110.11) ; R116.1 v1(81.38,112.14) ; C28.2 v1(91.31,44.96) ; v1(130.05,93.93) v1(130.05,91.69) ; R115.1 v1(81.38,110.61)
  BOTTOM w0.203: 162,47.47 162,46.25 v1(161.85,46.1) ; 61.11,97.28 62.18,97.28 ; 67.11,97.26 68.15,97.26 ; 149.99,46.35 149.99,44.2 ; 160.02,45.59 160.02,44.45 ; 63.07,97.33 64.29,97.33 ; 130,48.09 129.9,47.99 129.9,47.4 129.91,47.38 129.91,46.62 129.9,46.6 v1(129.9,46.15) ; 136.02,91.44 136.02,90.55 ; 137.97,46.51 137.97,47.55 ; 136.02,89.41 136.02,88.52 ; 165.99,46.48 165.99,47.5 ; 172.09,46.48 172.09,47.5 171.96,47.62 ; 163.96,89.41 163.96,88.52 164.08,88.39 ; 60.58,97.76 60.58,98.91 ; 69.01,97.31 70.31,97.31 ; 10.62,57.56 10.57,57.51 10.57,56.44 ; 9.98,55.88 9.14,55.88 ; 57.07,97.28 58.14,97.28 ; 65.1,97.33 66.12,97.33 ; 171.96,45.47 171.96,44.45 ; 131.95,89.41 131.95,88.27 ; v1(127.91,46.13) 127.91,46.61 127.91,46.62 127.91,47.38 127.91,47.39 127.91,48.03 127.97,48.09 ; 60.2,97.31 59.11,97.31 ; 71.15,97.28 72.34,97.28 ; 126.06,47.93 125.98,47.85 v1(125.98,46.35) ; 58.62,97.82 58.62,98.88 ; 72.92,97.31 74.27,97.31 ; 133.99,89.41 133.99,88.14 ; 138,45.49 138,44.45 ; 118.29,45.9 119.58,45.9 ; 60.63,96.85 60.63,95.68 ; 160.02,46.35 160.02,47.5 ; 169.93,47.78 169.93,46.48
  BOTTOM w0.254: 120.24,70.94 121.87,70.94 ; v1(122.86,68.86) 122.73,68.99 122.22,68.99 ; 158.01,49.28 158.01,45.77 ; 176.05,47.73 176.05,44.22 ; v1(125.98,46.35) 125.6,45.97 ; 156.01,49.61 156.01,46.1
  BOTTOM w0.279: 132.33,43.97 132.08,44.22 v1(132.08,45.97) 132.08,47.9 131.89,48.09 ; v1(127.91,46.13) 127.97,46.19 127.97,48.09 ; 124.03,47.93 124.03,46.35 v1(123.8,46.13) ; 170.69,46 176.4,46 ; 126.14,48.01 126.06,47.93 126.06,46.58 126.14,46.51 v1(125.98,46.35) ; v1(129.9,46.15) 130,46.25 130,48.09
  BOTTOM w0.305: v1(130.05,91.69) 130.33,91.97 132.05,91.97 ; v1(130.05,91.69) 129.83,91.91 128.24,91.91 v1(128.02,91.69) ; v1(130.05,91.69) 130.05,90.42 ; 120.06,90.09 119.89,89.92 ; v1(42.82,53.75) 42.82,53.62 42.82,53.61 LCD1.29 ; 125.98,87.25 v1(125.73,87) ; 8.51,57.91 10.16,57.91 ; 154.05,46.23 154.05,47.88 ; 10.54,83.82 11.94,83.82 ; v1(38.32,69.47) LCD3.20 v1(38.32,65.55) ; LCD1.20 v1(38.32,53.75) ; 152.02,45.72 152.02,44.2 ; 169.93,89.66 169.93,87.88 ; 10.03,83.82 8.38,83.82 ; 10.54,87.88 13.08,87.88 v1(13.21,88.01) ; 12.19,91.82 12.06,91.95 10.67,91.95 ; 10.54,75.82 12.45,75.82 ; 8.51,63.88 10.16,63.88 ; 10.54,95.89 12.32,95.89 ; 120.85,92.05 121.14,92.05 121.15,92.04 ; v1(128.02,91.69) 127.67,92.04 126.33,92.04 v1(125.98,91.69) ; v1(128.02,91.69) 128.02,90.3 ; 10.54,81.92 12.06,81.92 ; v1(130.18,87.38) 130.05,87.5 130.05,89.53 ; 119.89,74.96 118.36,74.96 ; 119.89,74.96 119.91,74.98 119.91,76.89 120.02,76.99 ; 119.89,74.96 121.79,74.96 ; 58.55,95.76 58.55,97.28 ; 10.54,79.88 12.19,79.88 ; 8.38,61.85 10.16,61.85 ; 133.96,91.97 134.01,91.92 134.01,90.5 ; 133.96,91.97 132.05,91.97 ; 133.96,91.97 135.79,91.97 136.02,91.74 136.02,91.44 ; 122.22,68.99 120.02,68.99 ; 120.02,68.99 118.52,68.99 ; 120.02,68.99 119.99,69.01 119.99,71.01 TINY210.C20 ; 12.32,59.82 12.27,59.87 10.72,59.87 10.67,59.82 ; 121.92,89.66 121.92,88.14 ; v1(8.38,65.91) 10.03,65.91 ; 121.92,90.17 121.92,91.37 121.38,91.91 121.27,91.91 121.15,92.04 ; v1(122.81,78.99) 122.78,79.02 119.89,79.02 ; v1(122.81,76.83) 122.66,76.99 120.02,76.99 ; 48.01,53.7 v1(48.01,53.77) ; 48.01,53.7 48.01,53.44 47.82,53.25 LCD1.39 ; 48.01,53.7 48.32,53.38 LCD1.40 ; 12.19,73.91 v1(10.54,73.91) ; 9.91,79.88 8.51,79.88 ; 10.16,69.85 v1(8.51,69.85) ; 8.64,93.85 v1(10.29,93.85) 12.06,93.85 ; 68.58,97.66 68.58,99.31 ; 10.54,65.91 12.19,65.91 ; 119.89,79.02 118.41,79.02 ; 119.89,79.02 120.02,78.89 ; 10.54,67.82 12.06,67.82 ; 10.16,75.82 8.51,75.82 ; 66.55,95.63 66.55,97.28 ; 8.38,59.82 8.43,59.87 10.11,59.87 10.16,59.82 ; 10.03,85.85 8.38,85.85 ; 171.96,89.66 171.96,88.14 ; 132.05,91.97 132.05,90.45 ; 152.02,46.23 152.02,47.75 ; 10.16,67.82 8.64,67.82 ; 170.05,90.42 170.05,91.95 ; v1(51.18,53.75) 51.18,53.21 50.82,52.85 LCD1.45 ; 64.64,95.63 64.64,97.16 ; 66.55,97.66 66.55,99.19 ; 64.64,97.79 64.64,99.19 64.52,99.31 ; 120.02,81 120.02,78.89 ; 120.02,81 118.47,81 ; 120.02,81 122.66,81 v1(122.81,81.15) ; 120.02,78.89 120.02,76.99 ; 123.95,89.66 123.95,88.14 ; v1(123.95,91.82) 123.85,91.82 123.63,92.04 122.64,92.04 122.05,91.44 121.45,92.04 121.15,92.04 ; v1(123.95,91.82) 124.17,92.04 125.73,92.04 125.98,91.78 v1(125.98,91.69) ; v1(123.95,91.82) 123.95,90.55 ; 10.03,73.91 v1(8.38,73.91) ; 120.02,76.99 118.47,76.99 ; v1(128.16,87.89) 128.02,88.04 128.02,89.53 ; 9.91,87.88 8.51,87.88 8.38,87.76 ; 125.98,89.66 125.98,88.01 ; 149.99,47.88 149.99,46.35 ; 125.98,90.3 v1(125.98,91.69) ; 62.61,95.63 62.61,97.28 ; 153.92,45.59 153.92,44.07 ; LCD1.38 47.32,53.24 46.99,53.57 ; 10.54,57.91 12.06,57.91 ; 70.61,99.31 70.61,97.79 ; 173.99,45.59 173.99,44.2 ; 10.03,89.92 8.64,89.92 ; v1(33.98,49.79) 33.81,49.95 LCD1.11 ; 10.54,85.85 12.06,85.85 ; 62.61,97.79 62.61,99.19 ; 46.99,53.57 v1(46.99,53.75) ; 46.99,53.57 46.82,53.4 LCD1.37 ; v1(137.92,90.17) 137.92,88.01 ; 10.54,61.85 12.06,61.85 ; 10.03,71.88 8.51,71.88 ; 10.03,81.92 8.64,81.92 ; 72.64,97.79 72.64,99.31 ; 70.61,97.16 70.61,95.5 ; v1(42.04,69.47) 42.16,69.34 42.43,69.34 42.82,68.95 LCD3.29 42.82,65.55 v1(42.8,65.53) ; 171.96,91.69 171.96,90.3 ; 10.03,91.95 8.38,91.95 ; 10.67,89.92 12.19,89.92 ; v1(33.82,69.47) LCD3.11 v1(33.82,65.69) ; 10.54,63.88 12.32,63.88 ; 68.58,95.5 68.58,97.28 ; 173.99,47.75 173.99,46.23 ; 10.03,77.85 8.38,77.85 ; 10.67,71.88 12.06,71.88 ; 10.67,77.85 12.19,77.85 ; 149.99,44.2 v1(149.99,44.07) ; 10.54,69.85 12.57,69.85 ; 147.96,47.88 147.96,46.23 ; 72.64,97.03 72.64,95.38 ; 147.96,45.85 v1(147.96,44.2) ; 8.51,95.89 10.16,95.89
  BOTTOM w0.559: 70.69,17.41 CON2.6 69.44,19.18 ; 112.14,110.11 112.14,109.84 v1(112.17,109.82) 112.01,109.66 v1(112.01,108.71) 112.01,103.63 v1(110.87,102.49) 109.96,101.57 v1(109.96,97.41) 109.96,86.64 v1(112.59,84.01) 113.54,83.06 v1(113.54,79.19) ; v1(152.17,67.97) 151.26,67.97 151.23,67.94 CON10.3 ; v1(103.89,82.32) 103.89,82.17 105.66,80.39 v1(105.66,80.01) 107.06,78.61 v1(107.06,76.83) v1(107.06,74.04) ; 45.63,10.29 COM3.5 ; COM3.5 46.89,9.03 ; COM3.5 48.15,10.29 ; COM3.5 46.89,11.55 ; 2.77,80.5 K4.2 ; K4.2 3.83,81.56 ; K4.2 3.83,79.43 ; K4.2 4.9,80.5 ; 135.67,119.69 USBH2.6 ; USBH2.6 140.35,119.69 ; USBH2.6 138.01,117.35 ; 32.51,87.63 v1(32.51,86.61) ; 2.77,93.2 K2.2 ; K2.2 3.83,92.13 ; K2.2 4.9,93.2 ; K2.2 3.83,94.26 ; 26.05,47.02 LCD1.A ; LCD1.A 26.05,50.43 ; LCD1.A 24.1,48.72 ; LCD1.A 28.01,48.72 ; C145.2 42.72,72.21 ; C145.2 41.66,71.15 ; C145.2 40.59,72.21 ; USBH1.4 160.12,116.97 ; USBH1.4 157.61,116.97 ; USBH1.4 158.86,118.23 ; USBH1.4 158.86,115.71 ; H6.1 108.93,26 ; H6.1 106,23.07 ; H6.1 103.07,26 ; H6.1 106,28.93 ; v1(120.03,93.77) 120.63,94.37 123.76,94.37 124.21,93.93 v1(130.05,93.93) 140.34,93.93 ; CON5.2 17.96,17.53 ; CON5.2 16.77,16.33 ; CON5.2 15.57,17.53 ; CON5.2 16.77,18.72 ; 47.04,19.18 CON4.4 48.29,17.41 ; 111.86,58.58 115.06,55.37 115.06,55.27 114.81,55.02 114.81,52.32 113.41,50.93 ; 111.86,58.58 v1(109.73,60.71) 107.06,63.37 v1(107.06,64.01) v1(107.06,68.58) v1(107.06,72.64) ; 111.86,58.58 v1(111.89,58.58) ; 36.32,89.53 C77.2 37.21,90.42 ; H9.1 16.93,36 ; H9.1 14,33.07 ; H9.1 14,38.93 ; H9.1 11.07,36 ; 11.07,106 H10.1 ; H10.1 14,108.93 ; H10.1 16.93,106 ; H10.1 14,103.07 ; USBH3.5 116.22,10.11 ; USBH3.5 111.55,10.11 ; USBH3.5 113.89,7.77 ; USBH3.5 113.89,12.45 ; 85.89,17.41 CON1.4 84.63,19.18 ; RST.2 177.32,30.94 ; RST.2 176.25,32 ; RST.2 176.25,29.87 ; RST.2 175.19,30.94 ; CON10.6 151.81,74.59 ; CON10.6 150.47,74.59 150.5,74.62 v1(152.02,74.62) ; CON10.6 150.48,73.69 ; CON10.6 150.48,75.5 ; 169.93,53.97 CON10.12 ; CON10.12 171.48,55.52 ; CON10.12 171.48,52.42 ; CON10.12 173.02,53.97 ; 30.81,89.1 30.48,89.43 C75.2 ; LCD3.B 51.07,66.64 ; LCD3.B 49.12,64.94 ; LCD3.B 51.07,63.24 ; CON6.8 123.29,122.68 ; CON6.8 122.03,123.15 v1(120.47,124.71) ; CON6.8 122.03,120.92 ; CN1.2 12.2,13.53 ; CN1.2 10.88,12.1 ; CN1.2 13.52,12.1 ; CN1.2 12.2,10.68 ; 1.07,126 H2.1 ; H2.1 4,123.07 ; H2.1 6.93,126 ; H2.1 4,128.93 ; H14.1 126,113.93 ; H14.1 126,108.07 ; H14.1 123.07,111 ; H14.1 128.93,111 ; 172.69,81.63 CON10.13 ; CON10.13 v1(175.5,83.17) ; CON10.13 171.14,83.17 ; 3.83,98.48 K1.2 ; K1.2 3.83,100.61 ; K1.2 4.9,99.55 ; K1.2 2.77,99.55 ; K6.2 4.9,67.8 ; K6.2 3.83,66.73 ; K6.2 2.77,67.8 ; K6.2 3.83,68.86 ; K5.2 4.9,74.15 ; K5.2 3.83,75.21 ; K5.2 3.83,73.08 ; K5.2 2.77,74.15 ; CN1.3 12.02,9.1 ; CN1.3 10.7,7.68 ; CN1.3 10.7,10.53 ; CN1.3 9.38,9.1 ; v1(93.47,121.28) 95.94,118.81 102.32,118.81 105.15,115.99 108.17,115.99 v1(111.25,112.9) 112.01,112.14 112.01,111.42 112.14,111.29 ; LCD4.11 v1(13.33,64.88) 13.34,64.87 ; 100.67,125.61 CAMERA.20 101.74,124.55 ; 1.07,106 H7.1 ; H7.1 6.93,106 ; H7.1 4,103.07 ; v1(88.52,121.28) 88.52,121.16 v1(89.66,120.02) 98.07,111.61 100.86,111.61 v1(101.09,111.38) 101.09,110.91 v1(102.51,109.49) H13.1 ; H5.1 4,28.93 ; H5.1 6.93,26 ; H5.1 4,23.07 ; H5.1 1.07,26 ; K7.2 3.83,62.51 ; K7.2 3.83,60.38 ; K7.2 2.77,61.45 ; 126,28.93 H12.1 126,23.07 ; P1.4 31.92,114.05 ; P1.4 30.92,115.5 ; P1.4 30.92,112.6 ; P1.4 29.91,114.05 ; LCD4.29 12.62,82.88 ; 169.93,46.48 170.41,46 170.69,46 ; 117.65,72.57 118.22,72 TINY210.C20 119.01,72 119.76,71.25 ; CON5.3 14.23,18.72 ; CON5.3 14.23,16.33 ; CON5.3 13.03,17.53 ; CON5.3 15.42,17.53 ; 22.3,81.48 C142.2 ; C142.2 23.37,80.42 ; C142.2 24.43,81.48 ; 4,1.07 H1.1 ; H1.1 1.07,4 ; H1.1 6.93,4 ; H1.1 4,6.93 ; USBH3.4 123.97,14.09 ; USBH3.4 123.97,11.57 ; USBH3.4 125.23,12.83 ; USBH3.4 122.71,12.83 ; LCD4.37 12.77,90.88 ; v1(10.54,73.91) 9.59,72.96 LCD4.20 8.23,72.88 8.18,72.82 ; v1(113.54,75.44) v1(113.54,71.15) 113.54,68.12 114.76,66.9 v1(114.81,66.9) 114.81,66.85 v1(116.23,65.43) v1(117.73,63.93) ; 35.81,87.63 v1(35.81,86.49) ; 164.29,113.41 v1(164.29,114.73) ; SDIO.2 55.82,98.28 56.62,97.49 ; SDIO.2 55.59,99.35 ; SDIO.2 54.53,98.28 ; v1(29.84,86.87) 30.61,87.63 30.86,87.63 ; v1(116.59,59.82) 116.59,60.05 v1(112.89,63.74) v1(110.59,66.04) v1(110.59,74.04) v1(110.59,76.83) v1(110.59,80.52) 110.59,81.08 v1(109.35,82.32) 109.19,82.32 106.93,84.58 v1(106.93,84.71) 106,85.64 v1(106,89.48) v1(106,92.25) 106,94.49 105.97,94.52 v1(105.97,97.41) 105.97,105.97 H13.1 ; 34.39,89.33 34.42,89.36 C76.2 ; H3.1 176,128.93 ; H3.1 178.93,126 ; H3.1 176,123.07 ; H3.1 173.07,126 ; H13.1 106,108.93 ; H13.1 106,103.07 ; H13.1 103.07,106 ; C27.2 144.89,67.55 v1(143.13,67.55) ; K3.2 3.83,87.91 ; K3.2 2.77,86.85 ; K3.2 4.9,86.85 ; K3.2 3.83,85.78 ; H11.1 108.93,36 ; H11.1 106,33.07 ; H11.1 103.07,36 ; 162.02,92.04 156.78,97.28 156.58,97.28 156.54,97.32 144.81,97.32 142.64,99.49 v1(138.3,99.49) v1(132.97,99.49) 126.64,99.49 v1(126.63,99.5) ; LCD3.A 26.05,66.63 ; LCD3.A 24.1,64.93 ; LCD3.A 26.05,63.23 ; LCD3.A 28.01,64.93 ; USBH2.4 142.34,116.97 ; USBH2.4 141.08,115.71 ; USBH2.4 139.83,116.97 ; USBH2.4 141.08,118.23 ; LCD4.38 8.44,90.88 ; H8.1 6.93,111 ; H8.1 4,113.93 ; H8.1 1.07,111 ; USBH1.5 168.95,122.02 ; USBH1.5 168.95,117.35 ; USBH1.5 166.61,119.69 ; USBH1.5 171.29,119.69 ; USBH3.6 127.04,12.45 ; USBH3.6 124.71,10.11 ; USBH3.6 127.04,7.77 ; 34.16,87.63 v1(34.16,86.61) ; 53.57,47.04 LCD1.B ; LCD1.B 51.62,48.74 ; LCD1.B 55.53,48.74 ; LCD1.B 53.57,50.44 ; H4.1 176,6.93 ; H4.1 173.07,4 ; H4.1 176,1.07 ; H4.1 178.93,4 ; COM0.5 84.34,10.29 ; COM0.5 81.83,10.29 ; COM0.5 83.09,11.55 ; COM0.5 83.09,9.03 ; C148.2 v1(46.48,79.86) ; C148.2 47.55,81.48 ; C148.2 45.42,81.48 ; 158.13,119.69 USBH1.6 155.79,117.35 ; 3.83,54.03 K8.2 ; K8.2 3.83,56.16 ; K8.2 2.77,55.1 ; C144.2 v1(35.31,79.86) ; C144.2 34.24,81.48 ; C144.2 36.37,81.48 ; 126.14,48.01 126.46,48.01 126.55,48.09 131.89,48.09 133.86,50.06 v1(133.86,50.72) ; 70.66,126.78 SDIO.A ; SDIO.A 76.53,126.78 ; SDIO.A 73.59,123.85 ; 55.59,123.85 SDIO.B ; SDIO.B 58.53,126.78 ; SDIO.B 52.66,126.78 ; 128.89,122.19 W1.1 127.67,123.41 ; TINY210.A2 119,89.03 119.89,89.92 ; 32.54,89.26 32.51,89.28 C78.2 ; 58.21,19.18 CON3.4 59.47,17.41 ; LCD4.40 8.49,92.88 ; LCD4.39 12.58,92.88
  vias: v1(2.16,48.13) v1(2.16,39.88) v1(2.21,33.91) v1(2.67,118.24) v1(5.08,49.4) v1(5.31,72.49) v1(6.48,122.05) v1(6.48,115.7) v1(6.48,20.45) v1(7.24,47.62) v1(7.24,41.78) v1(7.37,39.88) v1(7.75,100.46) v1(7.75,7.75) v1(8,38.35) v1(8.26,36.45) v1(8.38,11.56) v1(9.02,33.15) v1(9.02,29.34) v1(9.02,23.62) v1(9.65,127.13) v1(9.65,2.03) v1(10.92,99.19) v1(11.05,51.31) v1(12.7,49.66) v1(12.83,48.13) v1(12.83,46.61) v1(12.83,45.09) v1(12.83,43.56) v1(12.83,42.04) v1(12.83,40.39) v1(13.08,84.71) v1(13.19,60.81) v1(13.41,91.03) v1(13.46,122.05) v1(13.56,79.88) v1(14.1,111.89) v1(14.1,7.75) v1(14.32,67.26) v1(14.73,94.74) v1(15.37,127.13) v1(15.37,101.73) v1(15.37,51.31) v1(15.37,49.66) v1(15.37,48.23) v1(15.37,46.61) v1(15.37,45.09) v1(15.37,43.56) v1(15.37,42.04) v1(15.37,40.39) v1(15.37,31.24) v1(15.37,25.53) v1(15.37,19.81) v1(15.37,2.03) v1(16,57.91) v1(16.6,61.3) v1(17.48,14.05) v1(17.68,63.9) v1(18.41,79.5) v1(18.52,82.78) v1(18.54,55.4) v1(18.54,7.75) v1(18.85,76.99) v1(19.5,58.39) v1(19.91,88.16) v1(20.45,122.05) v1(20.45,117.6) v1(20.45,113.16) v1(20.45,108.08) v1(20.45,98.55) v1(20.45,94.74) v1(20.53,61.11) v1(20.57,48.9) v1(20.7,50.42) v1(20.7,47.37) v1(20.7,45.85) v1(20.7,44.32) v1(20.7,42.8) v1(20.7,41.27) v1(21.08,2.03) v1(22.35,55.4) v1(22.35,22.99) v1(22.35,17.91) v1(23.24,58.32) v1(23.7,90.4) v1(23.75,68.9) v1(23.75,66.23) v1(23.88,78.11) v1(23.88,63.68) v1(24.26,61.11) v1(24.26,54.1) v1(24.89,122.05) v1(24.89,117.6) v1(24.89,113.16) v1(24.89,108.08) v1(24.89,98.55) v1(24.89,94.74) v1(25.53,89.03) v1(25.53,14.1) v1(25.53,6.48) v1(25.53,2.03) v1(25.55,56.34) v1(26.16,52.2) v1(26.16,26.16) v1(26.42,38.1) v1(27.43,78.11) v1(27.43,50.93) v1(27.69,68.9) v1(27.74,54.2) v1(28.14,91.97) v1(28.09,58.19) v1(28.24,65.41) v1(28.2,61.73) v1(28.7,89.03) v1(28.85,71.45) v1(29.34,127.13) v1(29.34,122.05) v1(29.34,117.6) v1(29.34,108.08) v1(29.34,103.63) v1(29.34,98.55) v1(29.34,94.74) v1(29.97,2.03) v1(30.23,38.1) v1(31.88,80.14) v1(31.88,77.6) v1(32.08,94.01) v1(32.51,26.16) v1(32.51,24.26) v1(33.15,18.39) v1(33.15,14.1) v1(33.78,127.13) v1(33.78,122.05) v1(33.78,117.6) v1(33.78,108.08) v1(33.78,103.63) v1(33.78,98.55) v1(33.78,6.48) v1(34.7,94.06) v1(34.67,38.1) v1(34.9,15.72) v1(35.05,2.03) v1(35.69,77.6) v1(35.81,25.65) v1(36.09,49.07) v1(37.72,13.97) v1(38.23,127.13) v1(38.23,122.05) v1(38.23,117.6) v1(38.23,113.16) v1(38.23,108.08) v1(38.23,103.63) v1(38.23,98.55) v1(38.23,94.74) v1(38.91,87.38) v1(38.99,20.42) v1(39.12,38.1) v1(39.5,80.14) v1(39.5,77.6) v1(39.62,24.89) v1(40.13,12.45) v1(40.13,2.03) v1(40.89,26.42) v1(41.02,44.7) v1(41.43,91.77) v1(41.53,21.08) v1(42.04,28.07) v1(42.29,48.92) v1(42.82,61.39) v1(42.82,58.85) v1(43.05,46.3) v1(43.05,15.62) v1(43.31,122.05) v1(43.31,117.6) v1(43.31,113.16) v1(43.31,108.08) v1(43.31,98.55) v1(43.31,94.74) v1(43.31,12.06) v1(43.56,38.1) v1(43.79,80.59) v1(43.87,85.12) v1(44.58,28.07) v1(44.58,2.03) v1(44.96,91.8) v1(45.21,44.7) v1(45.54,75.92) v1(47.5,48.92) v1(47.5,46.3) v1(48.13,58.86) v1(48.16,56.32) v1(48.39,122.05) v1(48.39,117.6) v1(48.39,113.16) v1(48.39,108.08) v1(48.39,98.55) v1(48.39,94.74) v1(48.39,80.14) v1(48.39,28.07) v1(48.39,24.26) v1(48.64,44.58) v1(48.77,90.09) v1(48.9,64.19) v1(49.02,61.42) v1(49.15,70.23) v1(49.23,87.05) v1(49.45,84.38) v1(50.29,2.03) v1(50.93,37.57) v1(51.26,78.16) v1(51.44,70.36) v1(52.07,67.16) v1(52.22,82.04) v1(52.2,28.07) v1(52.2,24.26) v1(52.3,73.28) v1(52.96,43.56) v1(53.47,122.05) v1(53.47,117.6) v1(53.47,113.16) v1(53.47,108.08) v1(53.47,103.63) v1(53.47,23.11) v1(53.59,46.23) v1(53.59,37.47) v1(54.25,94.97) v1(54.99,61.42) v1(54.99,58.86) v1(54.99,56.32) v1(54.99,53.77) v1(54.99,51.46) v1(55.27,77.22) v1(55.27,75.03) v1(56.01,37.57) v1(56.01,28.07) v1(56.13,46.3) v1(56.24,64.14) v1(56.41,92.48) v1(56.36,88.49) v1(56.64,19.18) v1(56.64,16.64) v1(56.64,2.03) v1(56.9,67.08) v1(57.4,70.48) v1(57.4,43.56) v1(57.51,37.59) v1(57.91,122.05) v1(57.91,117.6) v1(57.91,113.16) v1(57.91,108.08) v1(58.12,77.19) v1(58.67,100.84) v1(58.67,84.33) v1(58.8,80.52) v1(59.18,11.56) v1(59.18,6.48) v1(59.82,28.07) v1(59.82,22.99) v1(60.09,38.97) v1(60.83,67.16) v1(60.83,64.19) v1(60.83,61.42) v1(60.83,58.86) v1(60.83,56.32) v1(60.83,53.75) v1(60.83,51.46) v1(60.83,48.96) v1(60.96,46.3) v1(61.09,100.46) v1(61.09,72.14) v1(61.34,84.84) v1(61.72,2.03) v1(62.36,126.49) v1(62.36,122.05) v1(62.36,117.6) v1(62.36,113.16) v1(62.36,35.05) v1(62.36,16.64) v1(63.63,100.46) v1(63.98,93.19) v1(64.26,104.27) v1(64.26,31.88) v1(64.26,28.07) v1(64.64,23.24) v1(65.66,93.22) v1(66.8,126.49) v1(66.8,122.05) v1(66.8,117.6) v1(66.8,100.46) v1(66.8,2.03) v1(67.26,93.12) v1(67.84,85.06) v1(67.94,67.16) v1(68.07,64.19) v1(68.07,61.42) v1(68.07,58.86) v1(68.07,19.18) v1(68.07,16.64) v1(68.33,56.32) v1(68.33,46.3) v1(68.33,39.28) v1(68.43,35.2) v1(68.45,53.75) v1(68.45,51.46) v1(68.45,48.96) v1(68.71,113.16) v1(68.71,108.71) v1(68.71,104.27) v1(69.22,37.47) v1(69.47,93.73) v1(69.98,100.46) v1(69.98,80.14) v1(69.98,31.88) v1(69.98,24.26) v1(69.98,11.56) v1(69.98,6.48) v1(70.49,68.32) v1(71.25,122.05) v1(72.27,65.91) v1(72.39,93.47) v1(72.52,2.03) v1(72.9,119.76) v1(73.15,113.16) v1(73.15,108.71) v1(73.15,104.27) v1(73.15,100.46) v1(73.25,63.28) v1(73.28,39.28) v1(73.66,46.3) v1(73.79,48.96) v1(74.1,60.52) v1(74.27,87.81) v1(74.42,16.64) v1(74.52,57.31) v1(75.06,31.88) v1(75.06,28.07) v1(75.06,24.26) v1(75.95,13.97) v1(76.1,55.35) v1(76.33,100.46) v1(76.33,97.92) v1(76.33,95.38) v1(76.81,37.39) v1(76.96,121.41) v1(77.22,119.86) v1(77.22,75.05) v1(77.29,52.12) v1(77.6,104.27) v1(77.6,80.14) v1(78.36,89.79) v1(78.81,72.45) v1(78.87,2.03) v1(79.14,49.26) v1(79.38,69.34) v1(79.69,66.1) v1(80.04,62.83) v1(80.14,101.22) v1(80.14,92.84) v1(80.14,35.05) v1(80.14,31.88) v1(80.14,28.07) v1(80.14,24.26) v1(80.39,46.48) v1(80.77,124.59) v1(80.77,121.41) v1(81.49,60.75) v1(81.66,13.97) v1(82.04,94.74) v1(82.55,18.92) v1(82.62,57.46) v1(82.8,80.62) v1(84.15,77.78) v1(84.45,16.81) v1(84.58,23.62) v1(84.85,54.97) v1(85.22,102.74) v1(85.25,75.28) v1(85.22,31.88) v1(85.22,7.11) v1(85.22,2.03) v1(85.47,51.44) v1(85.6,108.97) v1(86.11,97.66) v1(86.11,87.63) v1(86.44,114.83) v1(86.44,42.52) v1(86.93,73.34) v1(87.12,81.92) v1(87.5,16.66) v1(87.76,44.83) v1(87.88,113.28) v1(87.88,110.24) v1(87.96,102.44) v1(87.98,70.77) v1(88.32,85.14) v1(89.55,68.8) v1(89.79,31.75) v1(90.07,42.49) v1(90.55,36.45) v1(90.73,16.61) v1(90.81,110.11) v1(90.75,24.33) v1(91.06,97.03) v1(91.06,48.9) v1(91.19,81.66) v1(92.2,2.03) v1(92.33,50.8) v1(92.58,30.48) v1(92.81,44.78) v1(93.73,53.98) v1(93.75,61.95) v1(94.11,10.92) v1(94.11,5.21) v1(94.54,16.64) v1(94.61,50.67) v1(94.61,24.51) v1(94.69,83.34) v1(94.87,32.38) v1(94.87,28.96) v1(95.07,115.65) v1(95.17,98.25) v1(95.48,61.29) v1(95.5,48.39) v1(95.89,102.49) v1(96.14,100.2) v1(96.11,20.65) v1(96.9,63.65) v1(97.56,101.3) v1(97.92,53.98) v1(97.92,43.56) v1(98.15,104.75) v1(98.42,61.01) v1(98.55,28.96) v1(98.68,68.12) v1(99.19,17.27) v1(99.31,57.53) v1(99.52,91.62) v1(99.95,37.52) v1(100.61,43.61) v1(101.35,48.01) v1(101.35,45.85) v1(101.6,50.8) v1(101.73,24.26) v1(101.73,2.67) v1(101.98,57.53) v1(101.98,17.4) v1(102.13,33.2) v1(102.62,124.33) v1(102.87,53.98) v1(103.3,69.52) v1(103.63,44.07) v1(103.63,20.19) v1(103.63,5.84) v1(104.34,16.66) v1(105.03,42.67) v1(105.18,76.83) v1(105.28,124.33) v1(105.41,109.09) v1(105.54,2.67) v1(105.56,51.21) v1(105.66,11.4) v1(106.43,114.05) v1(106.4,58.14) v1(106.43,53.98) v1(106.81,120.65) v1(107.44,19.94) v1(108.33,53.98) v1(108.71,49.91) v1(109.73,120.78) v1(109.73,58.37) v1(109.98,5.84) v1(110.11,47.37) v1(110.74,50.04) v1(110.95,10.13) v1(111,32.26) v1(111.25,27.94) v1(111.25,2.67) v1(111.89,14.73) v1(112.14,119) v1(112.27,24.38) v1(112.42,50.83) v1(113.11,124.59) v1(113.16,121.03) v1(113.54,49.28) v1(113.51,47.55) v1(113.79,20.45) v1(115.06,6.48) v1(115.19,54.36) v1(115.19,27.81) v1(115.32,115.7) v1(115.32,32.38) v1(115.44,36.83) v1(115.7,107.94) v1(115.7,44.96) v1(115.7,2.67) v1(116.2,20.95) v1(116.59,53.75) v1(116.71,114.55) v1(116.94,124.61) v1(116.89,70.76) v1(116.97,102.74) v1(117.35,120.79) v1(117.35,119) v1(117.6,46.03) v1(117.6,44.83) v1(117.78,69.72) v1(118.87,14.73) v1(119.13,27.81) v1(119.25,32.38) v1(119.58,48.31) v1(119.63,23.37) v1(120.78,10.29) v1(120.78,6.48) v1(120.78,2.67) v1(121.28,119) v1(122.22,58.14) v1(122.53,56.21) v1(122.68,19.94) v1(122.68,15.37) v1(122.81,87.78) v1(122.76,59.94) v1(123.32,120.9) v1(123.37,103.02) v1(123.95,58.17) v1(124.13,64.74) v1(124.21,62.36) v1(124.33,53.59) v1(124.46,16.64) v1(124.84,34.92) v1(125.73,126.62) v1(125.86,81.15) v1(125.86,79.12) v1(125.98,74.3) v1(125.98,71.12) v1(126.21,13.64) v1(126.49,6.48) v1(126.49,2.67) v1(126.75,52.96) v1(126.87,56.26) v1(127.13,29.34) v1(127.13,22.35) v1(127.43,65.05) v1(128.02,102.62) v1(128.78,124.08) v1(128.91,55.12) v1(129.51,51.61) v1(129.67,72.9) v1(129.79,63.63) v1(129.92,121.41) v1(130.05,109.47) v1(130.56,126.62) v1(130.68,104.9) v1(131.06,79.25) v1(131.39,61.75) v1(131.7,75.18) v1(132.46,103.25) v1(132.59,66.42) v1(132.72,38.73) v1(133.27,55.47) v1(133.48,124.08) v1(133.48,70.36) v1(133.48,60.2) v1(133.86,86.74) v1(133.99,43.94) v1(134.24,115.95) v1(134.24,71.12) v1(134.75,105.49) v1(134.75,78.23) v1(135.51,81.53) v1(136.14,127.38) v1(136.07,104.19) v1(136.91,113.28) v1(137.41,80.9) v1(137.54,63.88) v1(137.54,51.18) v1(137.59,43.99) v1(137.67,60.33) v1(138.05,45.97) v1(138.56,115.82) v1(138.68,68.96) v1(138.81,102.49) v1(139.32,110.87) v1(139.32,35.43) v1(139.32,33.02) v1(139.7,51.05) v1(139.95,76.58) v1(140.21,43.94) v1(140.34,66.93) v1(140.46,128.4) v1(140.46,123.95) v1(140.84,61.59) v1(141.1,58.93) v1(141.35,86.61) v1(141.35,63.88) v1(141.35,51.05) v1(141.48,33.15) v1(141.99,78.74) v1(142.49,43.94) v1(142.75,120.14) v1(143.13,61.09) v1(143.51,114.68) v1(144.91,75.56) v1(145.16,87.63) v1(145.54,128.4) v1(145.54,123.95) v1(145.92,119.89) v1(146.3,114.55) v1(146.3,51.05) v1(147.07,83.95) v1(147.19,87.5) v1(147.6,59.44) v1(147.8,74.75) v1(147.96,105.59) v1(148.39,67.61) v1(148.79,60.91) v1(149,65.37) v1(149.73,100.84) v1(149.73,56.08) v1(149.73,51.05) v1(149.86,80.26) v1(149.86,70.87) v1(149.99,128.4) v1(149.99,123.95) v1(150.24,87.38) v1(150.62,17.27) v1(150.62,7.75) v1(151.13,108.84) v1(151.64,83.82) v1(151.64,1.91) v1(151.89,20.45) v1(152.02,71.12) v1(151.99,53.29) v1(152.27,41.78) v1(152.91,43.56) v1(153.03,115.7) v1(153.03,37.85) v1(153.16,78.87) v1(153.54,121.03) v1(153.54,33.15) v1(153.75,13.56) v1(153.8,59.18) v1(153.8,23.62) v1(154.18,86.74) v1(154.43,128.4) v1(154.43,123.95) v1(154.43,75.69) v1(154.69,51.31) v1(154.81,112.39) v1(154.94,37.34) v1(155.07,28.19) v1(155.7,81.41) v1(155.8,93.88) v1(156.34,71.88) v1(156.34,61.72) v1(156.34,57.53) v1(156.57,15.85) v1(156.72,115.82) v1(156.84,68.2) v1(156.97,21.72) v1(157.1,42.55) v1(157.61,78.87) v1(157.99,87.25) v1(158.24,92.2) v1(158.88,128.4) v1(158.88,123.95) v1(158.88,74.42) v1(158.88,64.26) v1(158.88,7.11) v1(159.26,1.91) v1(159.51,70.61) v1(160.02,57.28) v1(160.15,85.22) v1(160.27,61.34) v1(160.78,82.04) v1(160.78,51.31) v1(160.78,16) v1(160.78,12.83) v1(161.16,40.64) v1(161.93,43.56) v1(162.05,87.12) v1(162.05,77.6) v1(162.05,73.15) v1(163.32,128.4) v1(163.32,123.95) v1(163.32,16) v1(163.58,37.21) v1(163.7,42.04) v1(163.96,85.22) v1(164.08,61.34) v1(165.23,80.77) v1(165.74,72.26) v1(165.86,19.18) v1(165.99,51.44) v1(166.12,87.25) v1(166.37,29.59) v1(167,65.02) v1(167.51,93.85) v1(167.64,2.16) v1(167.77,128.4) v1(167.77,123.95) v1(168.15,85.22) v1(168.15,48.39) v1(169.67,22.35) v1(169.67,19.18) v1(169.93,78.49) v1(170,57.15) v1(170.43,43.94) v1(170.94,65.02) v1(170.94,7.75) v1(171.27,87.35) v1(171.58,94.11) v1(171.83,36.58) v1(171.96,92.08) v1(172.09,51.44) v1(172.34,48.39) v1(173.23,32.89) v1(173.48,118.24) v1(173.48,111.89) v1(173.48,108.71) v1(173.48,104.27) v1(173.61,92.08) v1(173.56,87.5) v1(173.61,79.5) v1(173.86,17.4) v1(173.86,13.46) v1(173.86,9.4) v1(174.75,113.28) v1(174.75,111.89) v1(174.88,43.56) v1(176.28,41.91) v1(176.4,32.51) v1(176.91,92.84) v1(176.91,24.13) v1(176.99,84.76) v1(177.22,72.24) v1(177.29,20.45) v1(177.47,76.5) v1(177.8,17.27) v1(177.93,118.24) v1(177.93,113.79) v1(177.93,108.71) v1(177.93,104.27) v1(177.93,99.82) v1(178.05,30.1) v1(178.31,13.72) v1(178.31,9.65)
